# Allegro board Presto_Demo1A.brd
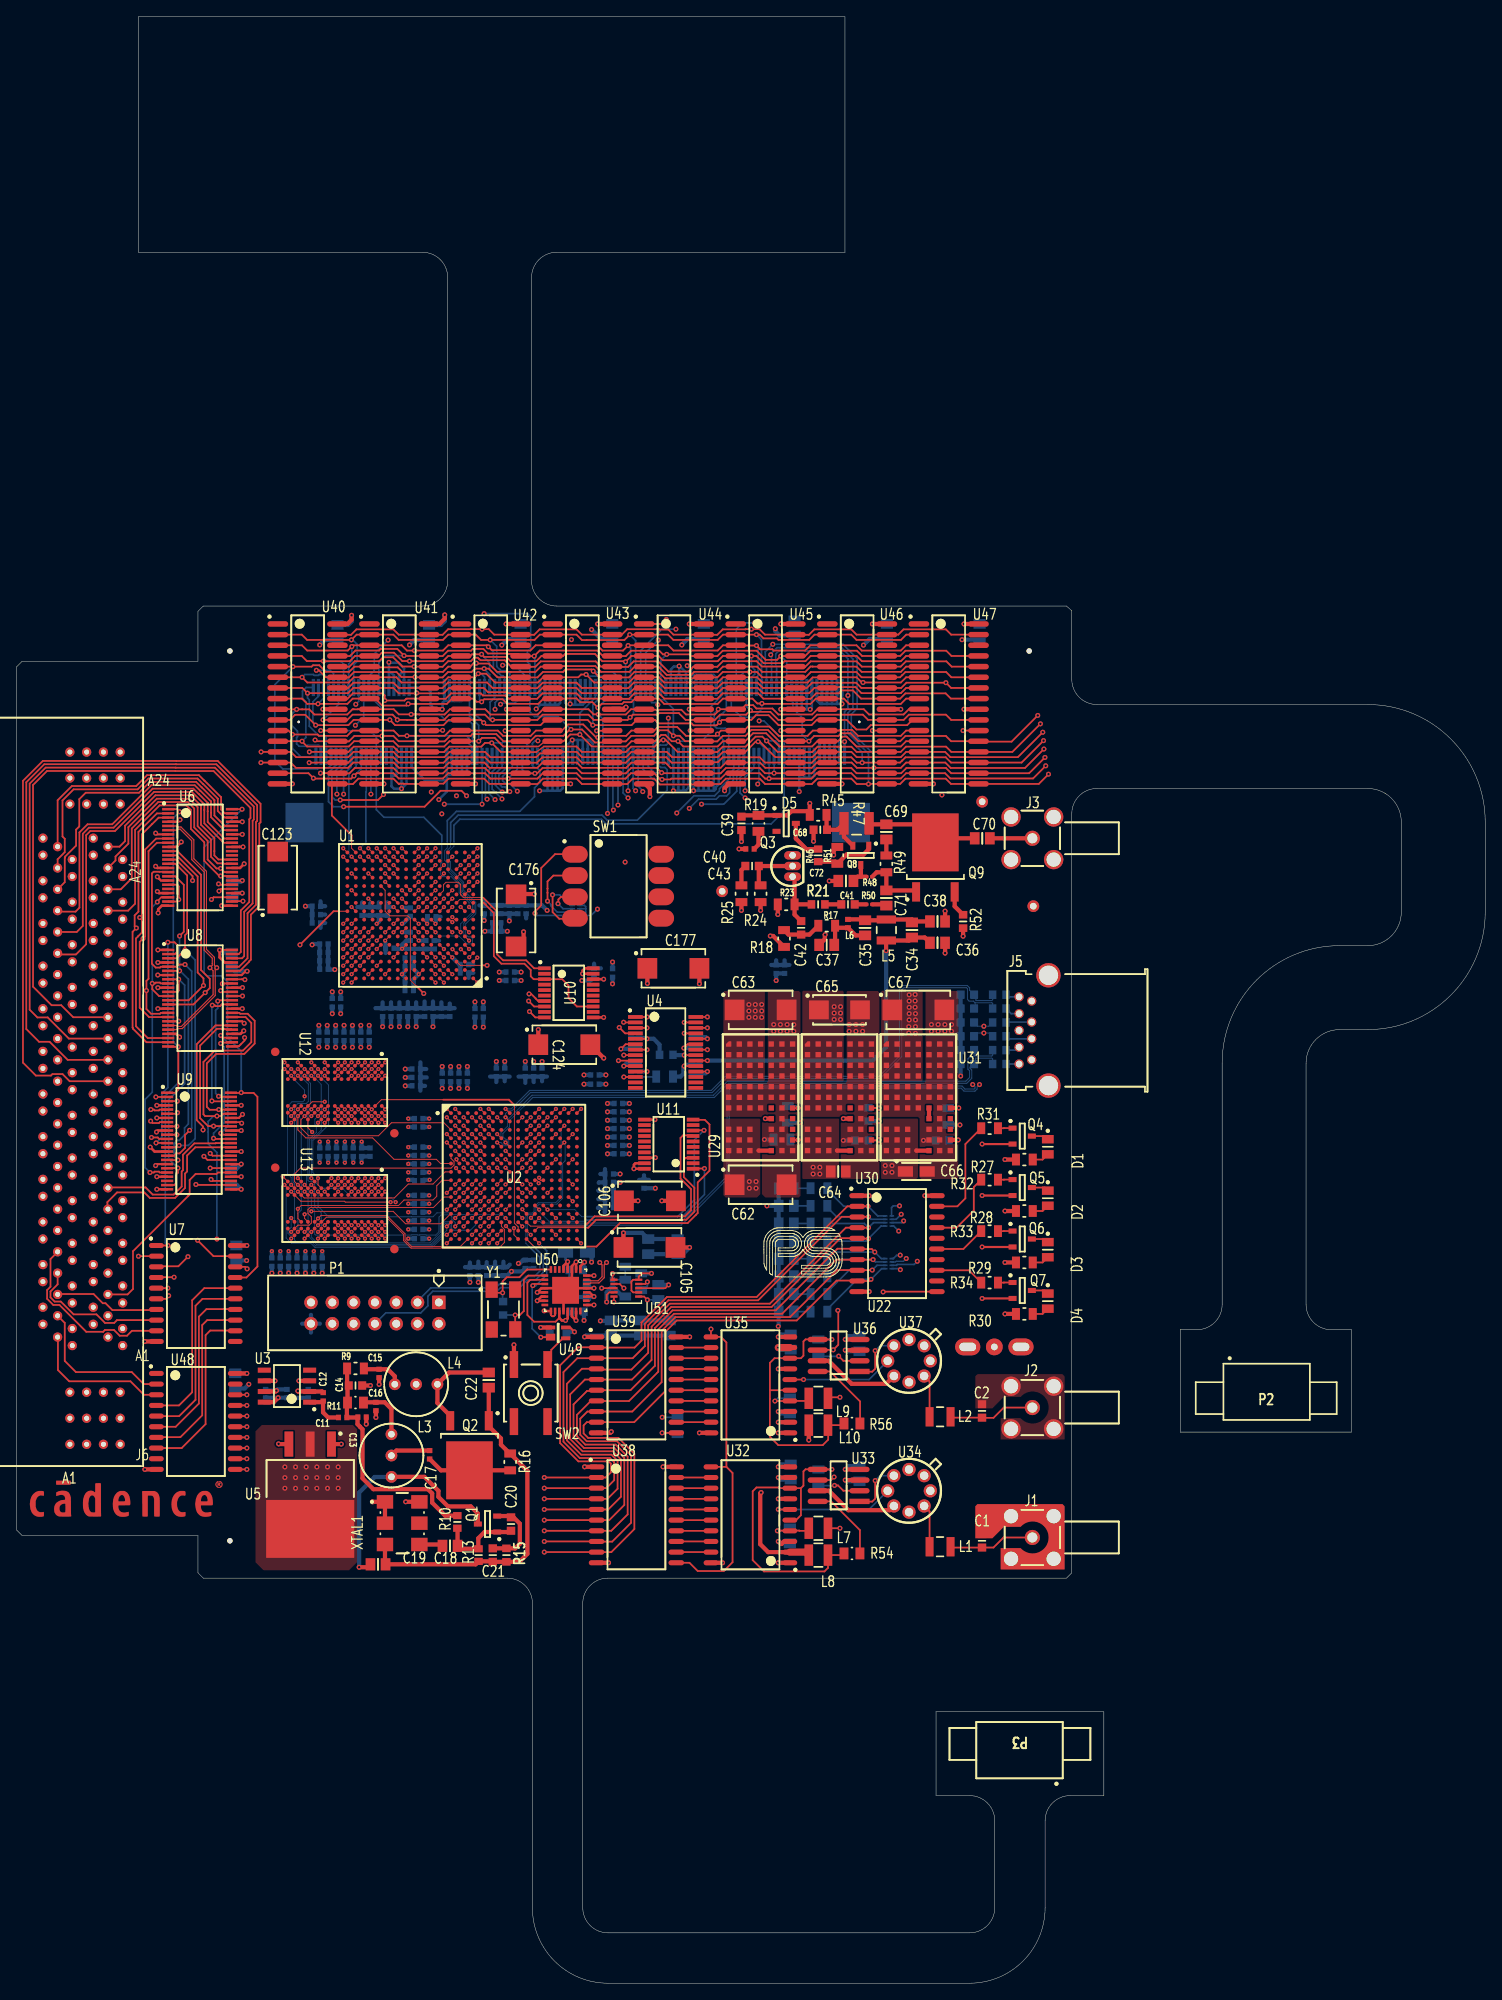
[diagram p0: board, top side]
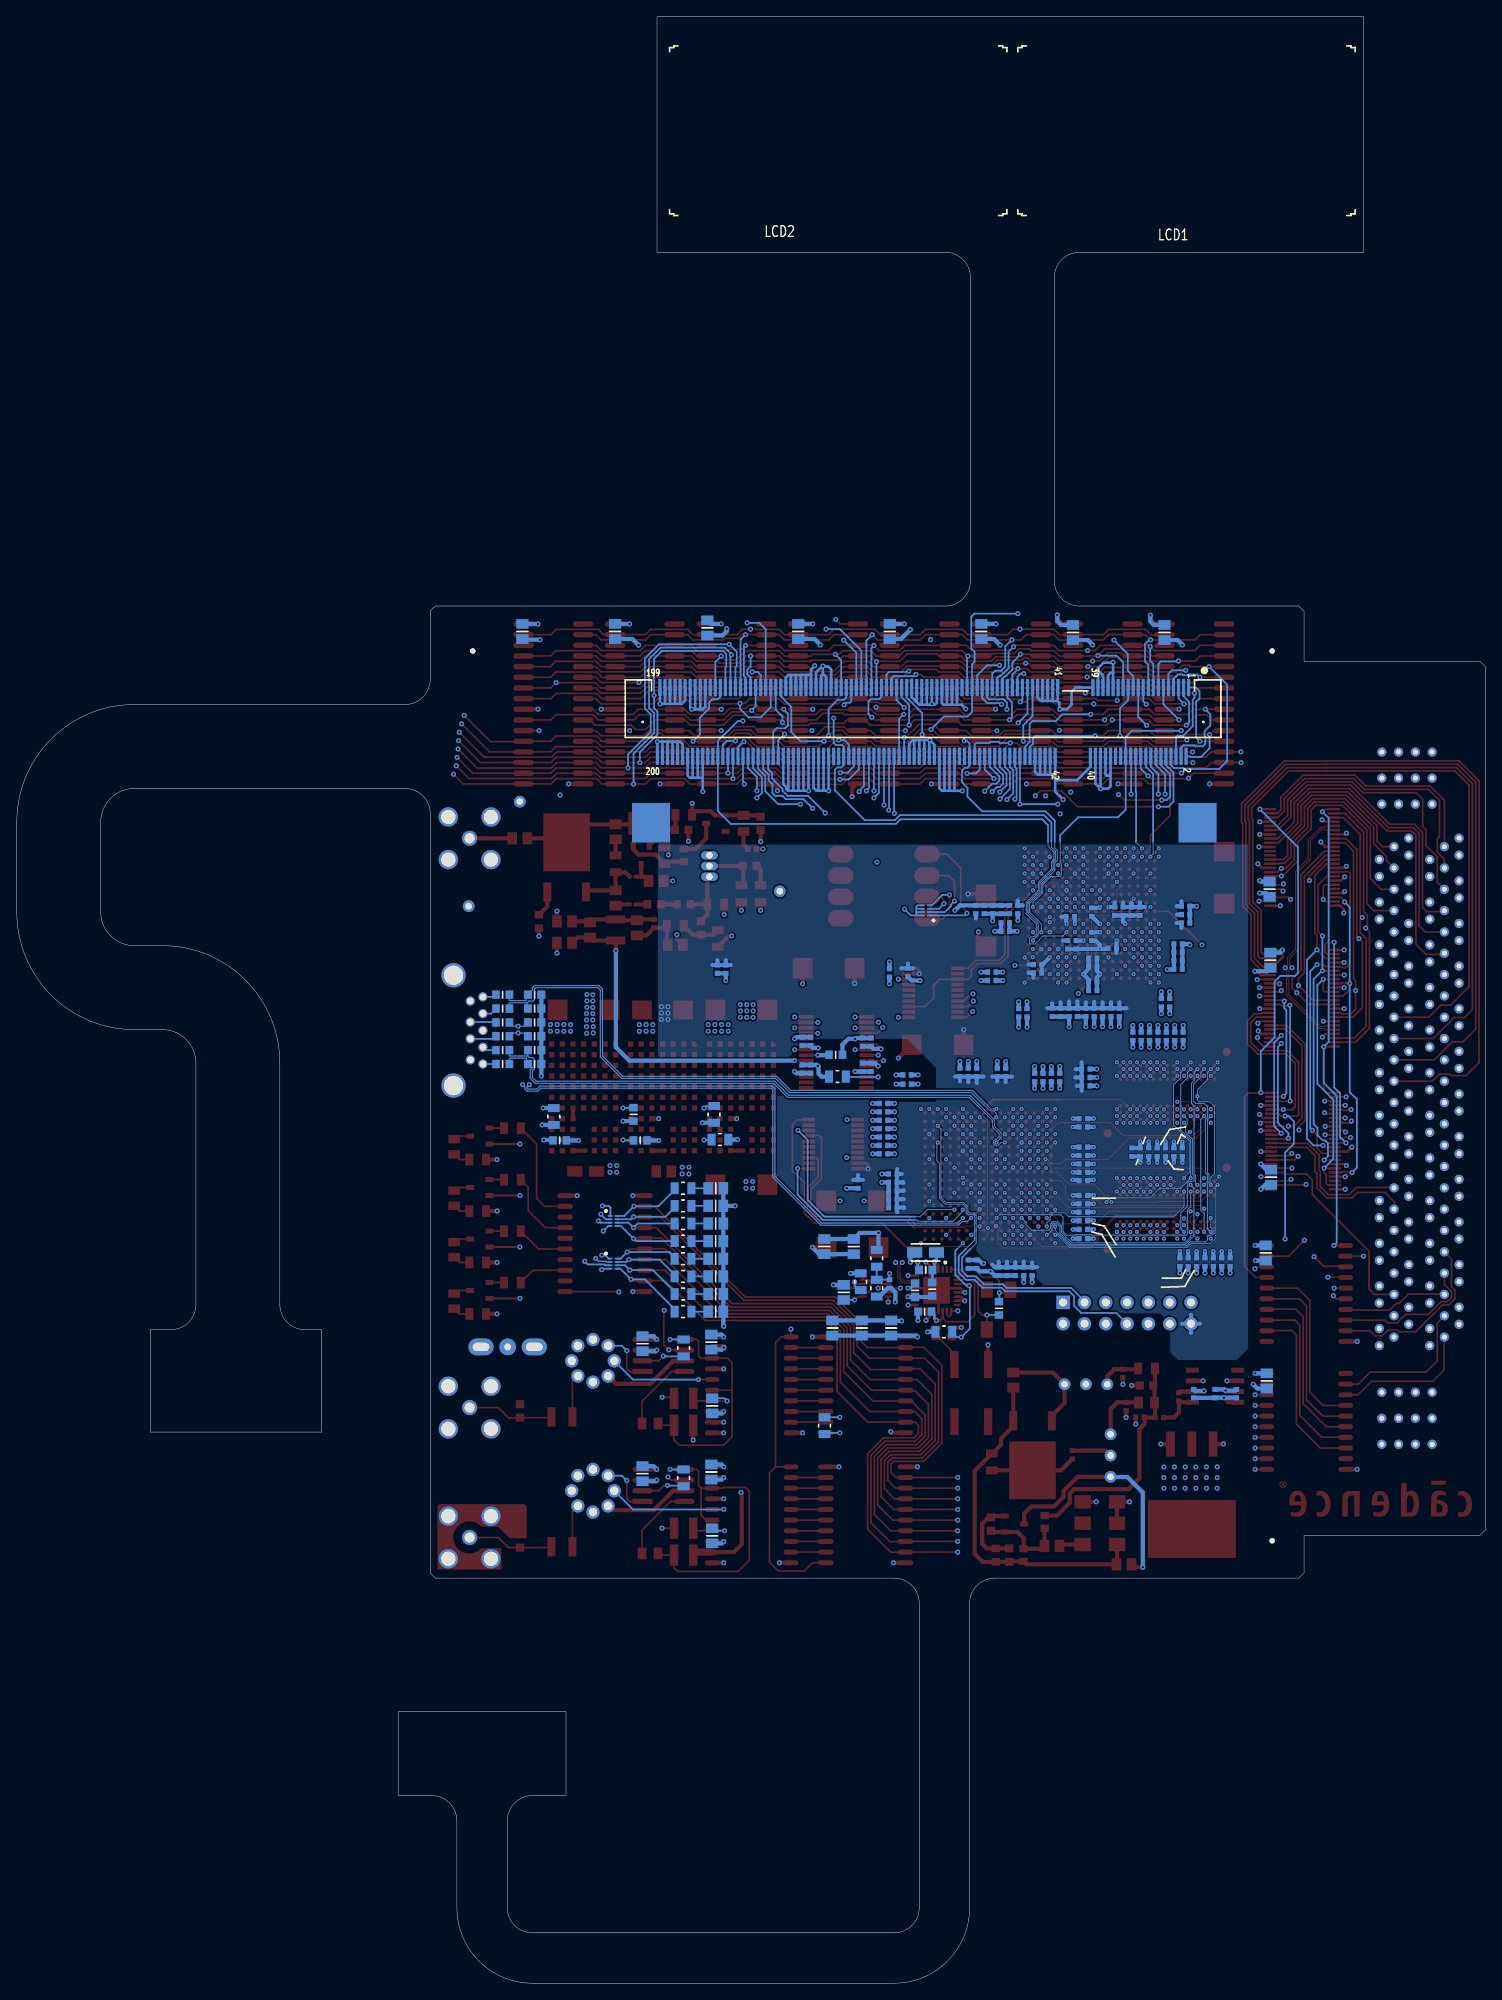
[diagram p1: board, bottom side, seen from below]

Outline 175 x 234.25 mm; copper layers: TOP, GND, INNER1, INNER2, POWER, BOTTOM. Coordinates in mm from the lower left corner of the outline.
Outline path: 0,156.84 0,53.97 0.63,53.34 21.59,53.34 21.59,48.89 22.22,48.26 58.45,48.26 arc(60.57,47.38) 61.45,45.26 61.45,9 arc(64.09,2.64) 70.45,0 113.55,0 arc(119.91,2.64) 122.55,9 122.55,19.35 arc(123.43,21.47) 125.55,22.35 129.55,22.35 129.55,32.35 109.55,32.35 109.55,22.35 113.55,22.35 arc(115.67,21.47) 116.55,19.35 116.55,9 arc(115.67,6.88) 113.55,6 70.45,6 arc(68.33,6.88) 67.45,9 67.45,45.26 arc(68.33,47.38) 70.45,48.26 125.09,48.26 125.73,48.89 125.73,139.32 arc(126.61,141.44) 128.73,142.32 161,142.32 arc(163.83,141.15) 165,138.32 165,127.6 arc(163.83,124.77) 161,123.6 157.65,123.6 arc(147.75,119.5) 143.65,109.6 143.65,80.85 arc(142.77,78.73) 140.65,77.85 138.65,77.85 138.65,65.65 159.05,65.65 159.05,77.85 156.65,77.85 arc(154.53,78.73) 153.65,80.85 153.65,109.6 arc(154.82,112.43) 157.65,113.6 161,113.6 arc(170.9,117.7) 175,127.6 175,138.32 arc(170.9,148.22) 161,152.32 128.73,152.32 arc(126.61,153.2) 125.73,155.32 125.73,163.49 125.09,164.06 64.35,164.06 arc(62.23,164.93) 61.35,167.06 61.35,203.2 arc(62.23,205.32) 64.35,206.2 98.7,206.2 98.7,234.25 14.5,234.25 14.5,206.2 48.35,206.2 arc(50.47,205.32) 51.35,203.2 51.35,167.06 arc(50.47,164.93) 48.35,164.06 22.22,164.06 21.59,163.42 21.59,157.48 0.63,157.48 0,156.84

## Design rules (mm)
constraint set DEFAULT: 
net group CLOCK: nets CLOCK+ CLOCK-
net group D: nets D+ D-
net group DATA1[0..9]: nets DATA1.CLKA DATA1.WSTAT_L
net group DP1: nets DIFF1+ DIFF1-
net group LED1: nets LED1 N828385
net group LED2: nets LED2 N852308
net group LED3: nets LED3 N852494
net group LED4: nets LED4 N852683
net group N62056: nets N62056 N62436
net group RF: nets DDS_OUT Q1E
net group STDA_SSRX: nets STDA_SSRX+ STDA_SSRX-
net group STDA_SSTX: nets STDA_SSTX+ STDA_SSTX-
net group VCLKC: nets CLKC VCLKC
net group ADDRESS: nets A0 A1 A2 A3 A4 A5 A6 A7 A8 A9 A10 A11 A12 A13 A14 A15 A16 A17 A18 A19 A20 A21 A22 A23
net group BUF_OUT: nets BUF_OUT N61996 N62230 N62316 N62564 N81780 N884986 Q2E
net group DATA: nets D0 D1 D2 D3 D4 D5 D6 D7 D9 D10 D11 D12 D13 D14 D15
net group DATA1.VD0: nets DATA1.VD0 N00671 VDX7
net group DATA1.VD1: nets DATA1.VD1 N00689 VDX6
net group DATA1.VD2: nets DATA1.VD2 N00703 VDX5
net group DATA1.VD3: nets DATA1.VD3 N00717 VDX4
net group DATA1.VD4: nets DATA1.VD4 N00827 VDX3
net group DATA1.VD5: nets DATA1.VD5 N00831 VDX2
net group DATA1.VD6: nets DATA1.VD6 N00835 VDX1
net group DATA1.VD7: nets DATA1.VD7 N00837 VDX0
net group DATA[0..20]: nets DATA.BA0 DATA.BA1 DATA.BA2 DATA.BA3 DATA.BD0 DATA.BD1 DATA.BD2 DATA.BD3 DATA.BD4 DATA.BD5 DATA.BD6 DATA.BD7 DATA.BD8 DATA.BD9 DATA.BD12 DATA.BD13 DATA.BD14 DATA.BD15 DATA.CLKB
net group DATA_DIFFS: nets DATA0+ DATA0- DATA1+ DATA1- DATA2+ DATA2- DATA3+ DATA3-
net group DDR_DQ: nets DDR_DQ0 DDR_DQ1 DDR_DQ2 DDR_DQ3 DDR_DQ4 DDR_DQ5 DDR_DQ6 DDR_DQ7 DDR_DQ8 DDR_DQ9 DDR_DQ10 DDR_DQ11 DDR_DQ12 DDR_DQ13 DDR_DQ14 DDR_DQ15 DDR_DQ16 DDR_DQ17 DDR_DQ18 DDR_DQ19 DDR_DQ20 DDR_DQ21 DDR_DQ22 DDR_DQ23 DDR_DQ24 DDR_DQ25 DDR_DQ26 DDR_DQ27 DDR_DQ28 DDR_DQ29 DDR_DQ30 DDR_DQ31
net group DDS[0..10]: nets DDS.DATA0 DDS.DATA1 DDS.DATA2 DDS.DATA3 DDS.DATA4 DDS.DATA5 DDS.DATA6 DDS.DATA7 DDS.FQUD DDS.RESET DDS.WCLK
net group MEMORY[0..29]: nets MEMORY.CTRL.RCS0 MEMORY.CTRL.RCS1 MEMORY.CTRL.RCS2 MEMORY.CTRL.RCS3 MEMORY.CTRL.RWE MEMORY.RA0 MEMORY.RA1 MEMORY.RA2 MEMORY.RA3 MEMORY.RA4 MEMORY.RA5 MEMORY.RA6 MEMORY.RA7 MEMORY.RA8 MEMORY.RA9 MEMORY.RA10 MEMORY.RA11 MEMORY.RA12 MEMORY.RA13 MEMORY.RA14 MEMORY.RA15 MEMORY.RA16 MEMORY.RD0 MEMORY.RD1 MEMORY.RD2 MEMORY.RD3 MEMORY.RD4 MEMORY.RD5 MEMORY.RD6 MEMORY.RD7
net group N00038_USER_DESIGN_OUTPUTS0_DAAMP0: nets N00038_USER_DESIGN_OUTPUTS0_DAAMP0 N00038_USER_DESIGN_OUTPUTS0_DAAMP1 N04966
net group N00046_USER_DESIGN_OUTPUTS0_DAAMP0: nets N00036_USER_DESIGN_OUTPUTS0_DAAMP0 N00046_USER_DESIGN_OUTPUTS0_DAAMP0 N00048_USER_DESIGN_OUTPUTS0_DAAMP0
net group N00046_USER_DESIGN_OUTPUTS0_DAAMP1: nets N00036_USER_DESIGN_OUTPUTS0_DAAMP1 N00046_USER_DESIGN_OUTPUTS0_DAAMP1 N00048_USER_DESIGN_OUTPUTS0_DAAMP1
net group N111881: nets N111502 N111881 N113142 N114006 N118214 N118917 N120412 N121910 N123723 N124926 N129422 N221560
net group POWER_GROUP: nets 5V
net group STEVE: nets N830942

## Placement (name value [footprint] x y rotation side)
C1  47 pF  [CAPC1608X86N]  115.03 52.7 90 top
C2  47 pF  [CAPC1608X86N]  115.03 68.17 90 top
C3  3300 pF  [CAPC2012X71N]  91.7 94.7 180 bottom
C4  3300 pF  [CAPC2012X71N]  91.7 86.3 180 bottom
C5  3300 pF  [CAPC2012X71N]  91.7 92.6 180 bottom
C6  3300 pF  [CAPC2012X71N]  91.7 84.2 180 bottom
C7  3300 pF  [CAPC2012X71N]  91.7 90.5 180 bottom
C8  3300 pF  [CAPC2012X71N]  91.7 82.1 180 bottom
C9  3300 pF  [CAPC2012X71N]  91.7 88.4 180 bottom
C10  3300 pF  [CAPC2012X71N]  91.7 80 180 bottom
C11  1000 pF  [CAPC1005X56N]  38.84 67.39 0 top
C12  1000 pF  [CAPC1005X56N]  36.52 69.85 270 top
C13  1000 pF  [CAPC1005X56N]  41.15 67.43 180 top
C14  0.01 uF  [CAPC1608X86N]  40.36 71.2 180 top
C15  1000 pF  [CAPC1005X56N]  43.18 72.64 90 top
C16  1000 pF  [CAPC1005X56N]  42.8 68.7 90 top
C17  1000 pF  [CAPC1005X56N]  49.2 62.95 270 top
C18  100 pF  [CAPC2012X70N]  51.63 52.1 180 top
C19  22 pF  [CAPC2012X71N]  43.05 49.9 0 top
C20  47 pF  [CAPC1608X86N]  58.9 54.7 90 top
C21  47 pF  [CAPC1608X86N]  56.73 51 90 top
C22  22 pF  [CAPC2012X71N]  56.25 71.85 270 top
C23  1000 pF  [CAPC1005X56N]  73.2 109.1 90 bottom
C24  1000 pF  [CAPC1005X56N]  81.4 108.9 90 bottom
C25  1000 pF  [CAPC1005X56N]  74.2 109.1 90 bottom
C26  1000 pF  [CAPC1005X56N]  80.4 108.9 90 bottom
C27  1000 pF  [CAPC1005X56N]  73.2 112.1 90 bottom
C28  1000 pF  [CAPC1005X56N]  80.4 112.2 90 bottom
C29  1000 pF  [CAPC1005X56N]  81.4 112.2 90 bottom
C30  1000 pF  [CAPC1005X56N]  74.2 112.1 90 bottom
C31  1000 pF  [CAPC1005X56N]  34.74 70.23 270 bottom
C32  1000 pF  [CAPC1005X56N]  32.2 70.23 270 bottom
C33  1000 pF  [CAPC1005X56N]  29.66 70.23 270 bottom
C34  3.3 pF  [CAPC2012X88N]  106.68 125.47 270 top
C35  8.2 pF  [CAPC2012X140N]  101.09 125.72 270 top
C36  22 pF  [CAPC2012X71N]  109.73 123.94 180 top
C37  22 pF  [CAPC2012X71N]  96.52 123.69 0 top
C38  33 pF  [CAPC2012X71N]  109.73 126.48 0 top
C39  0.01 uF  [CAPC1608X86N]  86.36 138.17 90 top
C40  1000 pF  [CAPC1005X56N]  87.38 135.12 0 top
C41  0.01 uF  [CAPC1608X86N]  99.06 128.51 0 top
C42  0.01 uF  [CAPC1608X86N]  93.47 125.72 90 top
C43  0.01 uF  [CAPC1608X86N]  87.63 133.09 0 top
C44  0.1 uF  [CAPC2012X100N]  25.53 96.01 270 bottom
C45  0.1 uF  [CAPC2012X100N]  26.16 86.99 270 bottom
C46  0.1 uF  [CAPC2012X100N]  25.6 121.86 90 bottom
C47  0.1 uF  [CAPC2012X100N]  25.7 130.33 270 bottom
C48  0.1 uF  [CAPC2012X100N]  92.7 161.45 270 bottom
C49  0.1 uF  [CAPC2012X100N]  49.13 160.9 270 bottom
C50  0.1 uF  [CAPC2012X100N]  103.7 161.03 270 bottom
C51  0.1 uF  [CAPC2012X100N]  60.05 161.03 270 bottom
C52  0.1 uF  [CAPC2012X100N]  81.88 161.03 270 bottom
C53  0.1 uF  [CAPC2012X100N]  38.22 160.9 270 bottom
C54  0.1 uF  [CAPC2012X100N]  70.96 161.03 270 bottom
C55  0.1 uF  [CAPC2012X100N]  114.74 161.03 270 bottom
C62  10 uF  [CAPMP7343X310N]  88.65 95.12 0 top
C63  100 uF  [CAPMP7343X310N]  88.65 115.95 0 top
C64  2.2 uF  [CAPC2012X71N]  97.9 96.7 0 top
C65  47 uF  [CAPMP6032X280N]  98.04 115.95 0 top
C66  4.7 uF  [CAPMP3216X180N]  107.2 96.7 0 top
C67  100 uF  [CAPMP7343X310N]  107.44 115.95 0 top
C68  0.01 uF  [CAPC1608X86N]  95.76 137.4 0 top
C69  0.47 uF  [CAPC2012X71N]  103.63 137.15 270 top
C70  0.47 uF  [CAPC2012X71N]  115.06 136.39 0 top
C71  0.47 uF  [CAPC2012X71N]  103.63 129.28 90 top
C72  0.01 uF  [CAPC2012X71N]  98.81 131.31 0 top
C73  22 pF  [CAPC1005X56N]  32.4 85.9 270 bottom
C74  22 pF  [CAPC1005X56N]  31.4 85.9 270 bottom
C75  22 pF  [CAPC1005X56N]  30.4 85.9 270 bottom
C76  22 pF  [CAPC1005X56N]  42.1 99 90 bottom
C77  22 pF  [CAPC1005X56N]  36.1 99 90 bottom
C78  22 pF  [CAPC1005X56N]  37.1 99 90 bottom
C79  22 pF  [CAPC1005X56N]  38.1 99 90 bottom
C80  22 pF  [CAPC1005X56N]  39.1 99 90 bottom
C81  220 pF  [CAPC1005X56N]  42 112.8 90 bottom
C82  220 pF  [CAPC1005X56N]  38 112.8 90 bottom
C83  220 pF  [CAPC1005X56N]  39 112.8 90 bottom
C84  220 pF  [CAPC1005X56N]  40 112.8 90 bottom
C85  2200 pF  [CAPC1005X56N]  47.9 95.6 180 bottom
C86  2200 pF  [CAPC1005X56N]  53.7 107.9 270 bottom
C87  2200 pF  [CAPC1005X56N]  51.7 107.9 270 bottom
C88  2200 pF  [CAPC1005X56N]  52.7 107.9 270 bottom
C89  22 pF  [CAPC1005X56N]  61.6 108.5 90 bottom
C90  22 pF  [CAPC1005X56N]  62.6 108.5 90 bottom
C91  22 pF  [CAPC1005X56N]  35.7 126.3 180 bottom
C92  22 pF  [CAPC1005X56N]  53.35 120.35 180 bottom
C93  22 pF  [CAPC1005X56N]  53.35 121.35 180 bottom
C94  22 pF  [CAPC1005X56N]  44.45 123.3 0 bottom
C95  22 pF  [CAPC1005X56N]  35.7 127.3 180 bottom
C96  22 pF  [CAPC1005X56N]  41.15 127.7 270 bottom
C97  22 pF  [CAPC1005X56N]  47.6 115.65 270 bottom
C98  22 pF  [CAPC1005X56N]  48.6 115.65 270 bottom
C99  220 pF  [CAPC1005X56N]  55 84.8 270 bottom
C100  220 pF  [CAPC1005X56N]  91.5 120.8 270 bottom
C101  220 pF  [CAPC1005X56N]  43.6 115.65 270 bottom
C102  220 pF  [CAPC1005X56N]  44.6 115.65 270 bottom
C103  220 pF  [CAPC1005X56N]  45.6 115.65 270 bottom
C104  220 pF  [CAPC1005X56N]  46.6 115.65 270 bottom
C105  470 uF  [CAPMP7343X430N]  75.4 87.65 0 top
C106  470 uF  [CAPMP7343X430N]  75.45 93.2 0 top
C107  22 pF  [CAPC1005X56N]  46.77 121.09 0 bottom
C108  22 pF  [CAPC1005X56N]  71 120.35 90 bottom
C109  22 pF  [CAPC1005X56N]  59.7 127.9 90 bottom
C110  22 pF  [CAPC1005X56N]  57.7 127.9 90 bottom
C111  22 pF  [CAPC1005X56N]  56.7 127.9 90 bottom
C112  220 pF  [CAPC1005X56N]  36.6 120.8 0 bottom
C113  220 pF  [CAPC1005X56N]  46.77 122.12 0 bottom
C114  220 pF  [CAPC1005X56N]  71.7 103.8 0 bottom
C115  2200 pF  [CAPC1005X56N]  71.7 101.8 0 bottom
C116  2200 pF  [CAPC1005X56N]  49.6 115.65 270 bottom
C117  220 pF  [CAPC1005X56N]  55.7 127.9 270 bottom
C118  220 pF  [CAPC1005X56N]  44.15 127.7 270 bottom
C119  220 pF  [CAPC1005X56N]  50.6 115.65 270 bottom
C120  2200 pF  [CAPC1005X56N]  42.15 127.7 270 bottom
C121  2200 pF  [CAPC1005X56N]  43.15 127.7 270 bottom
C122  2200 pF  [CAPC1005X56N]  49.75 123.7 270 bottom
C123  470 uF  [CAPMP7343X430N]  31.1 131.7 90 top
C124  470 uF  [CAPMP7343X430N]  65.25 111.8 0 top
C125  22 pF  [CAPC1005X56N]  47.9 103 180 bottom
C126  22 pF  [CAPC1005X56N]  47.9 102 180 bottom
C127  22 pF  [CAPC1005X56N]  46.9 124.7 270 bottom
C128  22 pF  [CAPC1005X56N]  46.9 127.6 270 bottom
C129  22 pF  [CAPC1005X56N]  57.2 126.31 0 bottom
C130  220 pF  [CAPC1005X56N]  55.6 115.6 270 bottom
C131  220 pF  [CAPC1005X56N]  54.6 115.6 270 bottom
C132  220 pF  [CAPC1005X56N]  37.6 116.8 270 bottom
C133  2200 pF  [CAPC1005X56N]  71.7 100.8 0 bottom
C134  22 pF  [CAPC1005X56N]  47.9 90.85 180 bottom
C135  22 pF  [CAPC1005X56N]  47.9 98.6 180 bottom
C136  22 pF  [CAPC1005X56N]  47.9 97.6 180 bottom
C137  22 pF  [CAPC1005X56N]  47.9 92.85 180 bottom
C138  22 pF  [CAPC1005X56N]  47.9 91.85 180 bottom
C139  22 pF  [CAPC1005X56N]  41 112.8 90 bottom
C140  220 pF  [CAPC1005X56N]  71.7 104.8 0 bottom
C141  220 pF  [CAPC1005X56N]  71.7 98.8 0 bottom
C142  2200 pF  [CAPC1005X56N]  47.9 99.6 180 bottom
C143  2200 pF  [CAPC1005X56N]  47.9 96.6 180 bottom
C144  22 pF  [CAPC1005X56N]  54 84.8 270 bottom
C145  22 pF  [CAPC1005X56N]  70.6 92.4 0 bottom
C146  22 pF  [CAPC1005X56N]  47.6 108.9 180 bottom
C147  22 pF  [CAPC1005X56N]  48.75 123.7 270 bottom
C148  22 pF  [CAPC1005X56N]  90.5 120.8 270 bottom
C149  22 pF  [CAPC1005X56N]  68.8 120.4 270 bottom
C150  22 pF  [CAPC1005X56N]  74.75 95.2 270 bottom
C151  22 pF  [CAPC1005X56N]  49.45 127.05 180 bottom
C152  22 pF  [CAPC1005X56N]  35.7 128.3 180 bottom
C153  22 pF  [CAPC1005X56N]  51.6 115.65 270 bottom
C154  220 pF  [CAPC1005X56N]  70.6 95.4 0 bottom
C155  220 pF  [CAPC1005X56N]  70.6 94.4 0 bottom
C156  220 pF  [CAPC1005X56N]  47.6 106.9 180 bottom
C157  220 pF  [CAPC1005X56N]  70.6 93.4 0 bottom
C158  220 pF  [CAPC1005X56N]  58.15 108.5 90 bottom
C159  220 pF  [CAPC1005X56N]  60.6 108.5 90 bottom
C160  22 pF  [CAPC1005X56N]  36.6 122.8 0 bottom
C161  22 pF  [CAPC1005X56N]  46.77 119.29 0 bottom
C162  22 pF  [CAPC1005X56N]  58.7 127.9 90 bottom
C163  22 pF  [CAPC1005X56N]  36.6 123.8 0 bottom
C164  22 pF  [CAPC1005X56N]  46.77 118.26 0 bottom
C165  220 pF  [CAPC1005X56N]  58.8 120.45 0 bottom
C166  220 pF  [CAPC1005X56N]  58.8 119.45 0 bottom
C167  220 pF  [CAPC1005X56N]  36.6 121.8 0 bottom
C168  2200 pF  [CAPC1005X56N]  71.7 102.8 0 bottom
C169  2200 pF  [CAPC1005X56N]  60.7 127.9 90 bottom
C170  220 pF  [CAPC1005X56N]  56 84.8 270 bottom
C171  220 pF  [CAPC1005X56N]  47.6 107.9 180 bottom
C172  220 pF  [CAPC1005X56N]  57.15 108.5 90 bottom
C173  2200 pF  [CAPC1005X56N]  70.6 96.4 0 bottom
C174  2200 pF  [CAPC1005X56N]  58 84.8 270 bottom
C175  2200 pF  [CAPC1005X56N]  57 84.8 270 bottom
C176  470 uF  [CAPMP7343X430N]  59.5 126.6 270 top
C177  470 uF  [CAPMP7343X430N]  78.25 120.9 0 top
C178  22 pF  [CAPC1005X56N]  60.6 85.65 270 bottom
C179  22 pF  [CAPC1005X56N]  47.9 89.8 180 bottom
C180  22 pF  [CAPC1005X56N]  47.9 88.7 180 bottom
C181  22 pF  [CAPC1005X56N]  68.9 107.1 180 bottom
C182  22 pF  [CAPC1005X56N]  68.9 108.2 180 bottom
C183  220 pF  [CAPC1005X56N]  57.2 125.31 0 bottom
C184  220 pF  [CAPC1005X56N]  38.6 116.8 270 bottom
C185  220 pF  [CAPC1005X56N]  61.6 85.65 270 bottom
C186  2200 pF  [CAPC1005X56N]  71.7 99.8 0 bottom
C187  22 pF  [CAPC1005X56N]  36.4 85.9 270 bottom
C188  22 pF  [CAPC1005X56N]  40.1 99 90 bottom
C189  22 pF  [CAPC1005X56N]  34.4 85.9 270 bottom
C190  22 pF  [CAPC1005X56N]  33.4 85.9 270 bottom
C191  22 pF  [CAPC1005X56N]  41.1 99 90 bottom
C192  22 pF  [CAPC1005X56N]  35.4 85.9 270 bottom
C193  220 pF  [CAPC1005X56N]  36 112.8 90 bottom
C194  220 pF  [CAPC1005X56N]  37 112.8 90 bottom
C195  2200 pF  [CAPC1005X56N]  50.7 107.9 270 bottom
C196  2200 pF  [CAPC1005X56N]  47.9 93.85 180 bottom
C197  0.1 uF  [CAPC2012X100N]  92.23 60.9 90 bottom
C198  0.1 uF  [CAPC2012X100N]  92.13 53.3 270 bottom
C199  0.1 uF  [CAPC2012X100N]  100.43 60.7 270 bottom
C200  0.1 uF  [CAPC2012X100N]  92.23 76.38 90 bottom
C201  0.1 uF  [CAPC2012X100N]  92.13 68.78 270 bottom
C202  0.1 uF  [CAPC2012X100N]  100.43 76.18 270 bottom
C2000  33 pF  [CAPC1608X86N]  113.28 114.45 180 bottom
C2001  33 pF  [CAPC1608X86N]  113.28 112.8 180 bottom
C2002  33 pF  [CAPC1608X86N]  113.28 116.11 180 bottom
C2003  33 pF  [CAPC1608X86N]  113.28 117.76 180 bottom
C2004  33 pF  [CAPC1608X86N]  113.28 109.5 180 bottom
C2005  33 pF  [CAPC1608X86N]  113.28 111.15 180 bottom
C2006  0.1 uF  [CAPC2012X100N]  26.04 71.75 270 bottom
C2007  0.01 uF  [CAPC1608X86N]  67.94 82.55 270 bottom
C2008  22 uF  [CAPMP3216X120N]  66.7 87.05 0 bottom
C2009  0.01 uF  [CAPC1608X86N]  66.67 84.96 0 bottom
C2010  1000 pF  [CAPC1005X56N]  70.99 83.31 270 bottom
C2011  0.1 uF  [CAPC2012X100N]  77.8 78.05 270 bottom
C2012  0.1 uF  [CAPC2012X100N]  74.3 78.05 270 bottom
C2013  0.1 uF  [CAPC2012X100N]  70.8 78.05 270 bottom
C2014  0.1 uF  [CAPC2012X100N]  78.75 87.75 270 bottom
C2015  0.1 uF  [CAPC2012X100N]  75.25 87.75 270 bottom
C2016  0.1 uF  [CAPC2012X100N]  76.45 82.29 90 bottom
D1  GREEN  [LEDC2012X120N]  122.87 99.64 270 top
D2  GREEN  [LEDC2012X120N]  122.87 93.51 270 top
D3  GREEN  [LEDC2012X120N]  122.87 87.38 270 top
D4  GREEN  [LEDC2012X120N]  122.87 81.25 270 top
D5  MMBD4148  [SOT95P230X109-3N]  91.69 138.17 0 top
J1  901-9894-RFX  [SMB_90]  121.03 53.1 270 top
J2  901-9894-RFX  [SMB_90]  121.03 68.58 270 top
J3  901-9894-RFX  [SMB_90]  121.03 136.39 270 top
J5  AU-Y1005-3-R  [USB3A_FEMALE]  119.45 113.5 90 top
J6  6367550-6  [C-1367550-6]  6.33 64.2 90 top
J7  1473005-1  [C_1_1473005_1_J1]  66.85 150.25 270 bottom
L1  47 nH  [INDC2520X220N]  110.03 52 0 top
L2  47 nH  [INDC2520X220N]  110.03 67.48 0 top
L3  INDUCTOR3  [TOROID01_3]  44.65 65.4 270 top
L4  INDUCTOR3  [TOROID01_3]  45.05 71.35 0 top
L5  1.0 uH  [INDC2520X220N]  103.63 125.47 90 top
L6  6.8 nH  [INDC1005X60N]  99.06 126.23 270 top
L7  56 nH  [IND_CENTRAL_1008]  95.53 54.2 180 top
L8  56 nH  [IND_CENTRAL_1008]  95.53 51 0 top
L9  56 nH  [IND_CENTRAL_1008]  95.53 69.68 180 top
L10  56 nH  [IND_CENTRAL_1008]  95.53 66.48 0 top
LCD1  S1D13742F01A200  [LCD_EA_8081-A3N-B]  35.6 220.68 180 bottom
LCD2  S1D13742F01A200  [LCD_EA_8081-A3N-B]  77.1 220.68 180 bottom
NOREF  -  []  25.4 52.7 0 top
NOREF#2  -  [unnamed#2]  116.5 75.8 0 top
NOREF#3  -  [unnamed#3]  120.65 158.7 0 top
NOREF#4  -  [unnamed#3]  25.4 158.7 0 top
NOREF#5  -  [unnamed#4]  70.6 121.7 0 top
NOREF#6  -  []  25.4 52.7 0 top
NOREF#7  -  [unnamed#3]  25.4 52.7 0 top
NOREF#8  -  []  -0.13 150.49 0 top
P1  TST-107-01-G-D  [SAMTEC_TST-107-XX-X-D]  50.3 81.1 180 top
P2  53261-0819  [MOLEX_53261-8_FITNAIL]  148.9 69.7 0 top
P3  53261-0819  [MOLEX_53261-8_FITNAIL]  119.55 28.51 180 top
Q1  2N2222AUB  [SOT95P230X109-3N]  56.1 54.7 180 top
Q2  MMBFJ310LT1G  [TO230P950X240-3N]  53.95 62.9 270 top
Q3  2N3866  [TO92]  92.46 131.82 180 top
Q4  KST3904  [SOT95P240X114-3N]  119.82 100.91 0 top
Q5  KST3904  [SOT95P240X114-3N]  119.82 94.78 0 top
Q6  KST3904  [SOT95P240X114-3N]  119.82 88.65 0 top
Q7  KST3904  [SOT95P240X114-3N]  119.82 82.52 0 top
Q8  2N3905  [SOT95P230X109-3N]  100.58 134.36 270 top
Q9  2N5179-NRC  [TO230P950X240-3N]  109.47 134.1 90 top
R1  243 Ohm  [RESC2012X60N]  95.6 94.7 0 bottom
R2  243 Ohm  [RESC2012X60N]  95.6 86.3 0 bottom
R3  243 Ohm  [RESC2012X60N]  95.6 92.6 0 bottom
R4  243 Ohm  [RESC2012X60N]  95.6 84.2 0 bottom
R5  243 Ohm  [RESC2012X60N]  95.6 90.5 0 bottom
R6  243 Ohm  [RESC2012X60N]  95.6 82.1 0 bottom
R7  243 Ohm  [RESC2012X60N]  95.6 88.4 0 bottom
R8  243 Ohm  [RESC2012X60N]  95.6 80 0 bottom
R9  330 Ohm  [RESC2012X60N]  40.36 73.23 180 top
R10  10 kOhm  [RESC1608X50N]  52.5 54.95 90 top
R11  97.6 Ohm  [RESC2012X70N]  40.36 69.17 0 top
R12  2.0 kOhm  [RESC1608X55N]  77.4 110.6 0 bottom
R13  10 kOhm  [RESC1608X50N]  55.03 51 90 top
R14  3.9 kOhm  [RESC2012X50N]  77.2 108 180 bottom
R15  2.0 kOhm  [RESC1608X55N]  58.35 51 90 top
R16  220 Ohm  [RESC2012X60N]  58.8 62.1 270 top
R17  180 Ohm  [RESC2012X60N]  96.52 125.97 180 top
R18  56 Ohm  [RESC2012X60N]  91.44 124.45 90 top
R19  97.6 Ohm  [RESC2012X70N]  88.39 138.17 90 top
R21  2.0 kOhm  [RESC1608X55N]  95.5 128.51 0 top
R23  470 Ohm  [RESC2012X60N]  91.69 128.51 0 top
R24  56 Ohm  [RESC2012X60N]  88.65 129.78 90 top
R25  56 Ohm  [RESC2012X60N]  86.36 129.78 90 top
R26  49.9 Ohm  [RESC2012X60N]  78.74 66.42 270 bottom
R27  470 Ohm  [RESC2012X60N]  120.08 98.12 0 top
R28  470 Ohm  [RESC2012X60N]  120.08 91.99 0 top
R29  470 Ohm  [RESC2012X60N]  120.08 85.86 0 top
R30  470 Ohm  [RESC2012X60N]  120.08 79.73 0 top
R31  150 Ohm  [RESC2012X60N]  115.94 101.85 0 top
R32  150 Ohm  [RESC2012X60N]  115.94 95.72 0 top
R33  150 Ohm  [RESC2012X60N]  115.94 89.59 0 top
R34  150 Ohm  [RESC2012X60N]  115.94 83.46 0 top
R39  105 kOhm  [RESC2012X60N]  91.9 103.5 270 bottom
R40  953 kOhm  [RESC2012X60N]  91.2 100.5 180 bottom
R41  61.9 kOhm  [RESC1608X55N]  101.5 103.5 270 bottom
R42  226 kOhm  [RESC1608X55N]  100.7 100.4 180 bottom
R43  118 kOhm  [RESC2012X60N]  111 103.25 270 bottom
R44  154 kOhm  [RESC1608X55N]  110.3 100.4 180 bottom
R45  470 Ohm  [RESC2012X60N]  95.5 139.18 180 top
R46  3.0 kOhm  [RESC1608X50N]  95.5 134.36 90 top
R47  270 Ohm  [RESC3225X70N]  100.08 138.17 180 top
R48  24 kOhm  [RESC0603X26N]  101.6 131.82 180 top
R49  470 Ohm  [RESC2012X60N]  103.63 133.34 90 top
R50  49.9 Ohm  [RESC0603X30N]  101.6 128.51 0 top
R51  6.8 kOhm  [RESC2012X60N]  97.79 134.36 90 top
R52  3.3 Ohm  [RESC1608X55N]  112.78 126.48 90 top
R53  97.6 Ohm  [RESC2012X50N]  95.53 60.2 270 bottom
R54  97.6 Ohm  [RESC2012X70N]  99.53 51.2 0 top
R55  97.6 Ohm  [RESC2012X50N]  95.53 75.68 270 bottom
R56  97.6 Ohm  [RESC2012X70N]  99.53 66.67 0 top
R2000  27.4 Ohm  [RESC1608X55N]  117.09 112.8 180 bottom
R2001  27.4 Ohm  [RESC1608X55N]  117.09 114.45 180 bottom
R2002  27.4 Ohm  [RESC1608X55N]  117.09 117.76 180 bottom
R2003  27.4 Ohm  [RESC1608X55N]  117.09 116.11 180 bottom
R2004  27.4 Ohm  [RESC1608X55N]  117.09 111.15 180 bottom
R2005  27.4 Ohm  [RESC1608X55N]  117.09 109.5 180 bottom
R2006  10  [RESC1608X55N]  65.91 82.67 90 bottom
R2007  2.0 kOhm  [RESC1608X55N]  66.8 80 0 bottom
R2008  100 kOhm  [RESC2012X60N]  64.52 77.59 180 bottom
R2009  2.0 kOhm  [RESC1608X55N]  57.95 80.4 90 bottom
R2010  10 kOhm  [RESC2012X60N]  72.52 86.36 270 bottom
R2011  10 kOhm  [RESC2012X60N]  72.52 82.8 270 bottom
R2012  100 kOhm  [RESC2012X60N]  74.42 83.56 270 bottom
RN1  47 Ohms  [RESNET_8]  66.65 127.8 0 bottom
RN2  100 Ohm  [RESNET_8]  103.89 85.72 180 bottom
RN3  100 Ohm  [RESNET_8]  103.89 90.8 180 bottom
SW1  76HPSB04GWRT  [SOIC254P1077X800-8M]  71.12 130.68 0 top
SW2  EVQPH  [SW_EVQ-PH_NO_GND]  61.25 70.3 0 top
U1  XC6SLX25-3FTG256  [FT256]  46.9 127.2 180 top
U2  XC6SLX25-3FTG256  [FT256]  59.25 96.15 0 top
U3  L78L08ACD13TR  [SOIC127P600X175-8N]  32.2 71.12 180 top
U4  AD9850BRSZ  [SOP65P780X200-28N]  77.32 110.88 0 top
U5  LM340  [TO254P1410X464-4N]  34.97 58.22 270 top
U6  74ALVT16245DGG,118  [SOP50P810X110-48N]  21.84 134.11 0 top
U7  74ACT245  [SOIC127P1028X265-20N]  21.34 82.16 0 top
U8  74ALVT16245DGG,118  [SOP50P810X110-48N]  21.84 117.34 0 top
U9  74ALVT16245DGG,118  [SOP50P810X110-48N]  21.72 100.33 0 top
U10  XCF01SVOG20C  [XCF01SVOG20]  65.79 117.98 0 top
U11  XCF01SVOG20C  [XCF01SVOG20]  77.7 99.95 180 top
U12  MT47H64M16HR-3:G TR  [MT47H128M]  37.9 106.1 270 top
U13  MT47H64M16HR-3:G TR  [MT47H128M]  37.9 92.3 270 top
U22  74HCT574  [SOIC127P1032X265-20AN]  104.9 88.1 0 top
U29  LTM8025EV#PBF  [LTUMODULE7X11]  88.65 105.53 0 top
U30  LTM8025EV#PBF  [LTUMODULE7X11]  98.04 105.53 0 top
U31  LTM8025EV#PBF  [LTUMODULE7X11]  107.44 105.53 0 top
U32  TLC5602CDWR  [SOIC127P1028X265-20N]  87.43 55.8 180 top
U33  DG419CY+  [SOG0508WG244L225]  100.43 57.4 90 top
U34  TLE2037AQDRG4Q1  [TO99]  106.33 61.2 180 top
U35  TLC5602CDWR  [SOIC127P1028X265-20N]  87.43 71.28 180 top
U36  DG419CY+  [SOG0508WG244L225]  100.43 72.88 90 top
U37  TLE2037AQDRG4Q1  [TO99]  106.33 76.68 180 top
U38  74HCT574  [SOIC127P1032X265-20AN]  73.84 55.8 0 top
U39  74HCT574  [SOIC127P1032X265-20AN]  73.84 71.28 0 top
U40  UPD431000AGW-B15  [SOJ127P866X375-32N]  34.66 152.39 0 top
U41  UPD431000AGW-B15  [SOJ127P866X375-32N]  45.58 152.39 0 top
U42  UPD431000AGW-B15  [SOJ127P866X375-32N]  56.49 152.39 0 top
U43  UPD431000AGW-B15  [SOJ127P866X375-32N]  67.41 152.39 0 top
U44  UPD431000AGW-B15  [SOJ127P866X375-32N]  78.32 152.39 0 top
U45  UPD431000AGW-B15  [SOJ127P866X375-32N]  89.23 152.39 0 top
U46  UPD431000AGW-B15  [SOJ127P866X375-32N]  100.15 152.39 0 top
U47  UPD431000AGW-B15  [SOJ127P866X375-32N]  111.06 152.39 0 top
U48  74ACT245  [SOIC127P1028X265-20N]  21.34 66.92 0 top
U49  MAX6711S  [SOT343N]  64.52 77.47 0 top
U50  NBC12429AMNR4G  [QFN50P500X500X100-33N]  65.41 82.55 270 top
U51  TPS51200DRCR  [DRC10_2P4X1P65]  72.64 82.8 0 top
XTAL1  100 MHz  [OSCSC254P500X700X200-6N]  45.93 54.8 0 top
Y1  20 MHz  [OSCCC350X600X120N]  58 80.25 0.2 top

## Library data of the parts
C1 = CAP: room: CHAN1
C2 = CAP: room: CHAN2
C3-C10 = CAP: signal model: DEFAULT_CAPACITOR_3300pF_1_2
C11-C13 C15-C17 C31-C33 = CAP: signal model: DEFAULT_CAPACITOR_1000pF_1_2
C14 = CAP: signal model: DEFAULT_CAPACITOR_10000pF_1_2
C18 = CAP: signal model: DEFAULT_CAPACITOR_100.000000pF_1_2
C19 C22 C73-C80 C89-C98 C125-C129 C134-C139 C144-C153 C178-C182 C187-C192 = CAP: signal model: DEFAULT_CAPACITOR_22.000000pF_1_2
C20 C21 = CAP: signal model: DEFAULT_CAPACITOR_47.000000pF_1_2
C23-C30 C107-C115 C160-C168 C2000-C2005 C2007 C2009-C2016 = CAP
C34-C43 = CAP: room: RF-AMP
C44-C47 C2006 = CAP: signal model: DEFAULT_CAPACITOR_100000pF_1_2
C48-C55 = CAP: signal model: DEFAULT_CAPACITOR_100000pF_1_2; room: BOTTOM_MEM
C62 = CAP_P: signal model: DEFAULT_CAPACITOR_1e+07pF_1_2
C63 = CAP_P: signal model: DEFAULT_CAPACITOR_1e+08pF_1_2
C64 = CAP: signal model: DEFAULT_CAPACITOR_2.2e+06pF_1_2
C65 = CAP_P: signal model: DEFAULT_CAPACITOR_4.7e+07pF_1_2
C66 = CAP_P: signal model: DEFAULT_CAPACITOR_4.7e+06pF_1_2
C67 C2008 = CAP_P
C68 C72 = CAP: signal model: DEFAULT_CAPACITOR_10000pF_1_2; room: RF-AMP
C69-C71 = CAP: signal model: DEFAULT_CAPACITOR_470000pF_1_2; room: RF-AMP
C81-C84 C99-C104 C117-C119 C130-C132 C140 C141 C154-C159 C170-C172 C183-C185 C193 C194 = CAP: signal model: DEFAULT_CAPACITOR_220.000000pF_1_2
C85-C88 C116 C120-C122 C133 C142 C143 C169 C173-C175 C186 C195 C196 = CAP: signal model: DEFAULT_CAPACITOR_2200pF_1_2
C105 C106 C123 C124 C176 C177 = CAP_P: signal model: DEFAULT_CAPACITOR_4.7e+08pF_1_2
C197-C199 = CAP: signal model: DEFAULT_CAPACITOR_100000pF_1_2; room: CHAN1
C200-C202 = CAP: signal model: DEFAULT_CAPACITOR_100000pF_1_2; room: CHAN2
D1-D4 = LED
D5 = DIODE_A_NC_C: room: RF-AMP
J1 = BNC-4: User Part Number: PSL-00000003; room: CHAN1
J2 = BNC-4: User Part Number: PSL-00000003; room: CHAN2
J3 = BNC-4: User Part Number: PSL-00000003
J5 = usb3a_female: User Part Number: PSL-00000013
J6 = CONN_C1367550_6
J7 = conn_dimm_200: room: BOTTOM_MEM
L1 = IND: room: CHAN1
L2 = IND: room: CHAN2
L3 L4 = INDUCTOR3
L5 L6 = IND: room: RF-AMP
L7 L8 = IND: signal model: DEFAULT_INDUCTOR_56.000000nH_1_2; room: CHAN1
L9 L10 = IND: signal model: DEFAULT_INDUCTOR_56.000000nH_1_2; room: CHAN2
LCD1 LCD2 = LCD-EA-8081-A3N
P1 = HDR_2X7_M
P2 P3 = HDR_1X8_M
Q1 Q4-Q7 = BJT_NPN_BEC
Q2 = MOSFET_I_EN_GSD
Q3 Q9 = BJT_NPN_BEC: room: RF-AMP
Q8 = BJT_PNP_BCE: room: RF-AMP
R1-R8 = RES: signal model: DEFAULT_RESISTOR_243.000000OHM_1_2
R9 = RES: signal model: DEFAULT_RESISTOR_330.000000OHM_1_2
R10 R13 = RES: signal model: DEFAULT_RESISTOR_10000OHM_1_2
R11 = RES: signal model: DEFAULT_RESISTOR_97.600000OHM_1_2
R12 R15 = RES: signal model: DEFAULT_RESISTOR_2000OHM_1_2
R14 = RES: signal model: DEFAULT_RESISTOR_3900OHM_1_2
R16 = RES: signal model: DEFAULT_RESISTOR_220.000000OHM_1_2
R17-R19 R21 R23-R25 = RES: room: RF-AMP
R26 = RES: signal model: DEFAULT_RESISTOR_49.900000OHM_1_2
R27-R30 = RES: signal model: DEFAULT_RESISTOR_470.000000OHM_1_2
R31-R34 = RES: signal model: DEFAULT_RESISTOR_150.000000OHM_1_2
R39 = RES: signal model: DEFAULT_RESISTOR_105000OHM_1_2
R40 = RES: signal model: DEFAULT_RESISTOR_953000OHM_1_2
R41 = RES: signal model: DEFAULT_RESISTOR_61900OHM_1_2
R42 = RES: signal model: DEFAULT_RESISTOR_226000OHM_1_2
R43 = RES: signal model: DEFAULT_RESISTOR_118000OHM_1_2
R44 = RES: signal model: DEFAULT_RESISTOR_154000OHM_1_2
R45 R49 = RES: signal model: DEFAULT_RESISTOR_470.000000OHM_1_2; room: RF-AMP
R46 = RES: signal model: DEFAULT_RESISTOR_3000OHM_1_2; room: RF-AMP
R47 = RES: signal model: DEFAULT_RESISTOR_270.000000OHM_1_2; room: RF-AMP
R48 = RES: signal model: DEFAULT_RESISTOR_24000OHM_1_2; room: RF-AMP
R50 = RES: signal model: DEFAULT_RESISTOR_49.900000OHM_1_2; room: RF-AMP
R51 = RES: signal model: DEFAULT_RESISTOR_6800OHM_1_2; room: RF-AMP
R52 = RES: signal model: DEFAULT_RESISTOR_3.300000OHM_1_2; room: RF-AMP
R53 R54 = RES: signal model: DEFAULT_RESISTOR_97.600000OHM_1_2; room: CHAN1
R55 R56 = RES: signal model: DEFAULT_RESISTOR_97.600000OHM_1_2; room: CHAN2
R2000-R2012 = RES
RN1 = RES_net_8
RN2 RN3 = RES_net_8: signal model: DEFAULT_RESISTOR_PACK_4_100.000000OHM
SW1 = SW DIP-4/SM
SW2 = SW_SPST_13_24
U1 = DemoG_Interface
U2 = DemoG_CoProc
U3 = LM78L05_SO8
U4 = AD9850
U5 = VREG_TGND
U6 U8 U9 = FCT16245
U7 U48 = 74-245_20P
U10 U11 = xcf01svog20
U12 U13 = MT47H64M16
U22 U38 U39 = FF_D_8X_OE3S_20P
U29-U31 = LTM8025
U32 = TLC5602A: room: CHAN1
U33 = DG419A: room: CHAN1
U34 = TLE2037A: room: CHAN1
U35 = TLC5602A: room: CHAN2
U36 = DG419A: room: CHAN2
U37 = TLE2037A: room: CHAN2
U40-U47 = uPD431000AGW-B15: room: MEM
U49 = MAX6711
U50 = NBC12429
U51 = TPS51200
XTAL1 = OSC_SEL383
Y1 = OSC4_24NC

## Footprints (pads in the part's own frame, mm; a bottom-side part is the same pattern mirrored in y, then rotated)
C-1367550-6
  round 1.1 hole 0.6: (0,0) (0,-2) (0,-4) (0,-6) (3.1,0) (3.1,-2) (3.1,-4) (3.1,-6) (6.2,0) (6.2,-2) (6.2,-4) (6.2,-6) (76.26,0) (76.26,-2) (76.26,-4) (76.26,-6) (79.36,0) (79.36,-2) (79.36,-4) (79.36,-6) (82.46,0) (82.46,-2) (82.46,-4) (82.46,-6) A1(11.755,-6.29) A2(13.785,-6.29) A3(16.835,-6.29) A4(18.865,-6.29) A5(21.915,-6.29) A6(23.945,-6.29) A7(26.995,-6.29) A8(29.025,-6.29) A9(32.075,-6.29) A10(34.105,-6.29) A11(37.155,-6.29) A12(39.185,-6.29) A13(42.235,-6.29) A14(44.265,-6.29) A15(47.315,-6.29) A16(49.345,-6.29) A17(52.395,-6.29) A18(54.425,-6.29) A19(57.475,-6.29) A20(59.505,-6.29) A21(62.555,-6.29) A22(64.585,-6.29) A23(67.635,-6.29) A24(69.665,-6.29) B1(12.77,-4.54) B2(15.31,-4.54) B3(17.85,-4.54) B4(20.39,-4.54) B5(22.93,-4.54) B6(25.47,-4.54) B7(28.01,-4.54) B8(30.55,-4.54) B9(33.09,-4.54) B10(35.63,-4.54) B11(38.17,-4.54) B12(40.71,-4.54) B13(43.25,-4.54) B14(45.79,-4.54) B15(48.33,-4.54) B16(50.87,-4.54) B17(53.41,-4.54) B18(55.95,-4.54) B19(58.49,-4.54) B20(61.03,-4.54) B21(63.57,-4.54) B22(66.11,-4.54) B23(68.65,-4.54) B24(71.19,-4.54) C1(14.295,-2.79) C2(16.325,-2.79) C3(19.375,-2.79) C4(21.405,-2.79) C5(24.455,-2.79) C6(26.485,-2.79) C7(29.535,-2.79) C8(31.565,-2.79) C9(34.615,-2.79) C10(36.645,-2.79) C11(39.695,-2.79) C12(41.725,-2.79) C13(44.775,-2.79) C14(46.805,-2.79) C15(49.855,-2.79) C16(51.885,-2.79) C17(54.935,-2.79) C18(56.965,-2.79) C19(60.015,-2.79) C20(62.045,-2.79) C21(65.095,-2.79) C22(67.125,-2.79) C23(70.175,-2.79) C24(72.205,-2.79) D1(11.755,-0.29) D2(13.785,-0.29) D3(16.835,-0.29) D4(18.865,-0.29) D5(21.915,-0.29) D6(23.945,-0.29) D7(26.995,-0.29) D8(29.025,-0.29) D9(32.075,-0.29) D10(34.105,-0.29) D11(37.155,-0.29) D12(39.185,-0.29) D13(42.235,-0.29) D14(44.265,-0.29) D15(47.315,-0.29) D16(49.345,-0.29) D17(52.395,-0.29) D18(54.425,-0.29) D19(57.475,-0.29) D20(59.505,-0.29) D21(62.555,-0.29) D22(64.585,-0.29) D23(67.635,-0.29) D24(69.665,-0.29) E1(12.77,1.46) E2(15.31,1.46) E3(17.85,1.46) E4(20.39,1.46) E5(22.93,1.46) E6(25.47,1.46) E7(28.01,1.46) E8(30.55,1.46) E9(33.09,1.46) E10(35.63,1.46) E11(38.17,1.46) E12(40.71,1.46) E13(43.25,1.46) E14(45.79,1.46) E15(48.33,1.46) E16(50.87,1.46) E17(53.41,1.46) E18(55.95,1.46) E19(58.49,1.46) E20(61.03,1.46) E21(63.57,1.46) E22(66.11,1.46) E23(68.65,1.46) E24(71.19,1.46) F1(14.295,3.21) F2(16.325,3.21) F3(19.375,3.21) F4(21.405,3.21) F5(24.455,3.21) F6(26.485,3.21) F7(29.535,3.21) F8(31.565,3.21) F9(34.615,3.21) F10(36.645,3.21) F11(39.695,3.21) F12(41.725,3.21) F13(44.775,3.21) F14(46.805,3.21) F15(49.855,3.21) F16(51.885,3.21) F17(54.935,3.21) F18(56.965,3.21) F19(60.015,3.21) F20(62.045,3.21) F21(65.095,3.21) F22(67.125,3.21) F23(70.175,3.21) F24(72.205,3.21)
C_1_1473005_1_J1
  round 0.3 hole 1.1 unplated: (0,-33.55) (0,33.25)
  rect 4.7x4.53 smd: (12,-32.565) (12,32.565)
  rect 2.05x0.38 smd: 1(-4.1,31.5) 2(4.1,31.2) 3(-4.1,30.9) 4(4.1,30.6) 5(-4.1,30.3) 6(4.1,30) 7(-4.1,29.7) 8(4.1,29.4) 9(-4.1,29.1) 10(4.1,28.8) 11(-4.1,28.5) 12(4.1,28.2) 13(-4.1,27.9) 14(4.1,27.6) 15(-4.1,27.3) 16(4.1,27) 17(-4.1,26.7) 18(4.1,26.4) 19(-4.1,26.1) 20(4.1,25.8) 21(-4.1,25.5) 22(4.1,25.2) 23(-4.1,24.9) 24(4.1,24.6) 25(-4.1,24.3) 26(4.1,24) 27(-4.1,23.7) 28(4.1,23.4) 29(-4.1,23.1) 30(4.1,22.8) 31(-4.1,22.5) 32(4.1,22.2) 33(-4.1,21.9) 34(4.1,21.6) 35(-4.1,21.3) 36(4.1,21) 37(-4.1,20.7) 38(4.1,20.4) 39(-4.1,20.1) 40(4.1,19.8) 41(-4.1,15.9) 42(4.1,15.6) 43(-4.1,15.3) 44(4.1,15) 45(-4.1,14.7) 46(4.1,14.4) 47(-4.1,14.1) 48(4.1,13.8) 49(-4.1,13.5) 50(4.1,13.2) 51(-4.1,12.9) 52(4.1,12.6) 53(-4.1,12.3) 54(4.1,12) 55(-4.1,11.7) 56(4.1,11.4) 57(-4.1,11.1) 58(4.1,10.8) 59(-4.1,10.5) 60(4.1,10.2) 61(-4.1,9.9) 62(4.1,9.6) 63(-4.1,9.3) 64(4.1,9) 65(-4.1,8.7) 66(4.1,8.4) 67(-4.1,8.1) 68(4.1,7.8) 69(-4.1,7.5) 70(4.1,7.2) 71(-4.1,6.9) 72(4.1,6.6) 73(-4.1,6.3) 74(4.1,6) 75(-4.1,5.7) 76(4.1,5.4) 77(-4.1,5.1) 78(4.1,4.8) 79(-4.1,4.5) 80(4.1,4.2) 81(-4.1,3.9) 82(4.1,3.6) 83(-4.1,3.3) 84(4.1,3) 85(-4.1,2.7) 86(4.1,2.4) 87(-4.1,2.1) 88(4.1,1.8) 89(-4.1,1.5) 90(4.1,1.2) 91(-4.1,0.9) 92(4.1,0.6) 93(-4.1,0.3) 94(4.1,0) 95(-4.1,-0.3) 96(4.1,-0.6) 97(-4.1,-0.9) 98(4.1,-1.2) 99(-4.1,-1.5) 100(4.1,-1.8) 101(-4.1,-2.1) 102(4.1,-2.4) 103(-4.1,-2.7) 104(4.1,-3) 105(-4.1,-3.3) 106(4.1,-3.6) 107(-4.1,-3.9) 108(4.1,-4.2) 109(-4.1,-4.5) 110(4.1,-4.8) 111(-4.1,-5.1) 112(4.1,-5.4) 113(-4.1,-5.7) 114(4.1,-6) 115(-4.1,-6.3) 116(4.1,-6.6) 117(-4.1,-6.9) 118(4.1,-7.2) 119(-4.1,-7.5) 120(4.1,-7.8) 121(-4.1,-8.1) 122(4.1,-8.4) 123(-4.1,-8.7) 124(4.1,-9) 125(-4.1,-9.3) 126(4.1,-9.6) 127(-4.1,-9.9) 128(4.1,-10.2) 129(-4.1,-10.5) 130(4.1,-10.8) 131(-4.1,-11.1) 132(4.1,-11.4) 133(-4.1,-11.7) 134(4.1,-12) 135(-4.1,-12.3) 136(4.1,-12.6) 137(-4.1,-12.9) 138(4.1,-13.2) 139(-4.1,-13.5) 140(4.1,-13.8) 141(-4.1,-14.1) 142(4.1,-14.4) 143(-4.1,-14.7) 144(4.1,-15) 145(-4.1,-15.3) 146(4.1,-15.6) 147(-4.1,-15.9) 148(4.1,-16.2) 149(-4.1,-16.5) 150(4.1,-16.8) 151(-4.1,-17.1) 152(4.1,-17.4) 153(-4.1,-17.7) 154(4.1,-18) 155(-4.1,-18.3) 156(4.1,-18.6) 157(-4.1,-18.9) 158(4.1,-19.2) 159(-4.1,-19.5) 160(4.1,-19.8) 161(-4.1,-20.1) 162(4.1,-20.4) 163(-4.1,-20.7) 164(4.1,-21) 165(-4.1,-21.3) 166(4.1,-21.6) 167(-4.1,-21.9) 168(4.1,-22.2) 169(-4.1,-22.5) 170(4.1,-22.8) 171(-4.1,-23.1) 172(4.1,-23.4) 173(-4.1,-23.7) 174(4.1,-24) 175(-4.1,-24.3) 176(4.1,-24.6) 177(-4.1,-24.9) 178(4.1,-25.2) 179(-4.1,-25.5) 180(4.1,-25.8) 181(-4.1,-26.1) 182(4.1,-26.4) 183(-4.1,-26.7) 184(4.1,-27) 185(-4.1,-27.3) 186(4.1,-27.6) 187(-4.1,-27.9) 188(4.1,-28.2) 189(-4.1,-28.5) 190(4.1,-28.8) 191(-4.1,-29.1) 192(4.1,-29.4) 193(-4.1,-29.7) 194(4.1,-30) 195(-4.1,-30.3) 196(4.1,-30.6) 197(-4.1,-30.9) 198(4.1,-31.2) 199(-4.1,-31.5) 200(4.1,-31.8)
CAPC1005X56N
  rect 0.6x0.65 smd: 1(-0.5,0) 2(0.5,0)
CAPC1608X86N
  rect 0.95x1 smd: 1(-0.8,0) 2(0.8,0)
CAPC2012X70N
  rect 1.15x1.45 smd: 1(-0.9,0) 2(0.9,0)
CAPC2012X71N
  rect 1.15x1.45 smd: 1(-0.9,0) 2(0.9,0)
CAPC2012X88N
  rect 1.15x1.45 smd: 1(-0.9,0) 2(0.9,0)
CAPC2012X100N
  rect 1.15x1.45 smd: 1(-0.9,0) 2(0.9,0)
CAPC2012X140N
  rect 1.15x1.45 smd: 1(-0.9,0) 2(0.9,0)
CAPMP3216X120N
  rect 1.8x1.25 smd: 1(-1.3,0) 2(1.3,0)
CAPMP3216X180N
  rect 1.8x1.25 smd: 1(-1.3,0) 2(1.3,0)
CAPMP6032X280N
  rect 2.35x2.25 smd: 1(-2.45,0) 2(2.45,0)
CAPMP7343X310N
  rect 2.35x2.45 smd: 1(-3.1,0) 2(3.1,0)
CAPMP7343X430N
  rect 2.35x2.45 smd: 1(-3.1,0) 2(3.1,0)
DRC10_2P4X1P65
  rect 0.85x0.28 smd: 1(-1.475,1) 2(-1.475,0.5) 3(-1.475,0) 4(-1.475,-0.5) 5(-1.475,-1) 6(1.475,-1) 7(1.475,-0.5) 8(1.475,0) 9(1.475,0.5) 10(1.475,1)
FT256
  round 0.45 smd: A1(-7.5,7.5) A2(-6.5,7.5) A3(-5.5,7.5) A4(-4.5,7.5) A5(-3.5,7.5) A6(-2.5,7.5) A7(-1.5,7.5) A8(-0.5,7.5) A9(0.5,7.5) A10(1.5,7.5) A11(2.5,7.5) A12(3.5,7.5) A13(4.5,7.5) A14(5.5,7.5) A15(6.5,7.5) A16(7.5,7.5) B1(-7.5,6.5) B2(-6.5,6.5) B3(-5.5,6.5) B4(-4.5,6.5) B5(-3.5,6.5) B6(-2.5,6.5) B7(-1.5,6.5) B8(-0.5,6.5) B9(0.5,6.5) B10(1.5,6.5) B11(2.5,6.5) B12(3.5,6.5) B13(4.5,6.5) B14(5.5,6.5) B15(6.5,6.5) B16(7.5,6.5) C1(-7.5,5.5) C2(-6.5,5.5) C3(-5.5,5.5) C4(-4.5,5.5) C5(-3.5,5.5) C6(-2.5,5.5) C7(-1.5,5.5) C8(-0.5,5.5) C9(0.5,5.5) C10(1.5,5.5) C11(2.5,5.5) C12(3.5,5.5) C13(4.5,5.5) C14(5.5,5.5) C15(6.5,5.5) C16(7.5,5.5) D1(-7.5,4.5) D2(-6.5,4.5) D3(-5.5,4.5) D4(-4.5,4.5) D5(-3.5,4.5) D6(-2.5,4.5) D7(-1.5,4.5) D8(-0.5,4.5) D9(0.5,4.5) D10(1.5,4.5) D11(2.5,4.5) D12(3.5,4.5) D13(4.5,4.5) D14(5.5,4.5) D15(6.5,4.5) D16(7.5,4.5) E1(-7.5,3.5) E2(-6.5,3.5) E3(-5.5,3.5) E4(-4.5,3.5) E5(-3.5,3.5) E6(-2.5,3.5) E7(-1.5,3.5) E8(-0.5,3.5) E9(0.5,3.5) E10(1.5,3.5) E11(2.5,3.5) E12(3.5,3.5) E13(4.5,3.5) E14(5.5,3.5) E15(6.5,3.5) E16(7.5,3.5) F1(-7.5,2.5) F2(-6.5,2.5) F3(-5.5,2.5) F4(-4.5,2.5) F5(-3.5,2.5) F6(-2.5,2.5) F7(-1.5,2.5) F8(-0.5,2.5) F9(0.5,2.5) F10(1.5,2.5) F11(2.5,2.5) F12(3.5,2.5) F13(4.5,2.5) F14(5.5,2.5) F15(6.5,2.5) F16(7.5,2.5) G1(-7.5,1.5) G2(-6.5,1.5) G3(-5.5,1.5) G4(-4.5,1.5) G5(-3.5,1.5) G6(-2.5,1.5) G7(-1.5,1.5) G8(-0.5,1.5) G9(0.5,1.5) G10(1.5,1.5) G11(2.5,1.5) G12(3.5,1.5) G13(4.5,1.5) G14(5.5,1.5) G15(6.5,1.5) G16(7.5,1.5) H1(-7.5,0.5) H2(-6.5,0.5) H3(-5.5,0.5) H4(-4.5,0.5) H5(-3.5,0.5) H6(-2.5,0.5) H7(-1.5,0.5) H8(-0.5,0.5) H9(0.5,0.5) H10(1.5,0.5) H11(2.5,0.5) H12(3.5,0.5) H13(4.5,0.5) H14(5.5,0.5) H15(6.5,0.5) H16(7.5,0.5) J1(-7.5,-0.5) J2(-6.5,-0.5) J3(-5.5,-0.5) J4(-4.5,-0.5) J5(-3.5,-0.5) J6(-2.5,-0.5) J7(-1.5,-0.5) J8(-0.5,-0.5) J9(0.5,-0.5) J10(1.5,-0.5) J11(2.5,-0.5) J12(3.5,-0.5) J13(4.5,-0.5) J14(5.5,-0.5) J15(6.5,-0.5) J16(7.5,-0.5) K1(-7.5,-1.5) K2(-6.5,-1.5) K3(-5.5,-1.5) K4(-4.5,-1.5) K5(-3.5,-1.5) K6(-2.5,-1.5) K7(-1.5,-1.5) K8(-0.5,-1.5) K9(0.5,-1.5) K10(1.5,-1.5) K11(2.5,-1.5) K12(3.5,-1.5) K13(4.5,-1.5) K14(5.5,-1.5) K15(6.5,-1.5) K16(7.5,-1.5) L1(-7.5,-2.5) L2(-6.5,-2.5) L3(-5.5,-2.5) L4(-4.5,-2.5) L5(-3.5,-2.5) L6(-2.5,-2.5) L7(-1.5,-2.5) L8(-0.5,-2.5) L9(0.5,-2.5) L10(1.5,-2.5) L11(2.5,-2.5) L12(3.5,-2.5) L13(4.5,-2.5) L14(5.5,-2.5) L15(6.5,-2.5) L16(7.5,-2.5) M1(-7.5,-3.5) M2(-6.5,-3.5) M3(-5.5,-3.5) M4(-4.5,-3.5) M5(-3.5,-3.5) M6(-2.5,-3.5) M7(-1.5,-3.5) M8(-0.5,-3.5) M9(0.5,-3.5) M10(1.5,-3.5) M11(2.5,-3.5) M12(3.5,-3.5) M13(4.5,-3.5) M14(5.5,-3.5) M15(6.5,-3.5) M16(7.5,-3.5) N1(-7.5,-4.5) N2(-6.5,-4.5) N3(-5.5,-4.5) N4(-4.5,-4.5) N5(-3.5,-4.5) N6(-2.5,-4.5) N7(-1.5,-4.5) N8(-0.5,-4.5) N9(0.5,-4.5) N10(1.5,-4.5) N11(2.5,-4.5) N12(3.5,-4.5) N13(4.5,-4.5) N14(5.5,-4.5) N15(6.5,-4.5) N16(7.5,-4.5) P1(-7.5,-5.5) P2(-6.5,-5.5) P3(-5.5,-5.5) P4(-4.5,-5.5) P5(-3.5,-5.5) P6(-2.5,-5.5) P7(-1.5,-5.5) P8(-0.5,-5.5) P9(0.5,-5.5) P10(1.5,-5.5) P11(2.5,-5.5) P12(3.5,-5.5) P13(4.5,-5.5) P14(5.5,-5.5) P15(6.5,-5.5) P16(7.5,-5.5) R1(-7.5,-6.5) R2(-6.5,-6.5) R3(-5.5,-6.5) R4(-4.5,-6.5) R5(-3.5,-6.5) R6(-2.5,-6.5) R7(-1.5,-6.5) R8(-0.5,-6.5) R9(0.5,-6.5) R10(1.5,-6.5) R11(2.5,-6.5) R12(3.5,-6.5) R13(4.5,-6.5) R14(5.5,-6.5) R15(6.5,-6.5) R16(7.5,-6.5) T1(-7.5,-7.5) T2(-6.5,-7.5) T3(-5.5,-7.5) T4(-4.5,-7.5) T5(-3.5,-7.5) T6(-2.5,-7.5) T7(-1.5,-7.5) T8(-0.5,-7.5) T9(0.5,-7.5) T10(1.5,-7.5) T11(2.5,-7.5) T12(3.5,-7.5) T13(4.5,-7.5) T14(5.5,-7.5) T15(6.5,-7.5) T16(7.5,-7.5)
IND_CENTRAL_1008
  rect 1.02x2.54 smd: 1(-1.145,0) 2(1.145,0)
INDC1005X60N
  rect 0.6x0.7 smd: 1(-0.5,0) 2(0.5,0)
INDC2520X220N
  rect 0.95x2.3 smd: 1(-1.25,0) 2(1.25,0)
LEDC2012X120N
  rect 1x1.4 smd: A(0.9,0) C(-0.9,0)
LTUMODULE7X11
  custom 0.159x0.159 smd: A1(-3.81,6.35)
  rect 0.635x0.635 smd: A2(-2.54,6.35) A3(-1.27,6.35) A4(0,6.35) A5(1.27,6.35) A6(2.54,6.35) A7(3.81,6.35) B1(-3.81,5.08) B2(-2.54,5.08) B3(-1.27,5.08) B4(0,5.08) B5(1.27,5.08) B6(2.54,5.08) B7(3.81,5.08) C1(-3.81,3.81) C2(-2.54,3.81) C3(-1.27,3.81) C4(0,3.81) C5(1.27,3.81) C6(2.54,3.81) C7(3.81,3.81) D1(-3.81,2.54) D2(-2.54,2.54) D3(-1.27,2.54) D4(0,2.54) D5(1.27,2.54) D6(2.54,2.54) D7(3.81,2.54) E1(-3.81,1.27) E2(-2.54,1.27) E3(-1.27,1.27) E4(0,1.27) E5(1.27,1.27) E6(2.54,1.27) E7(3.81,1.27) F1(-3.81,0) F2(-2.54,0) F3(-1.27,0) F4(0,0) F5(1.27,0) F6(2.54,0) F7(3.81,0) G1(-3.81,-1.27) G2(-2.54,-1.27) G3(-1.27,-1.27) G4(0,-1.27) G5(1.27,-1.27) G6(2.54,-1.27) G7(3.81,-1.27) H5(1.27,-2.54) H6(2.54,-2.54) H7(3.81,-2.54) J1(-3.81,-3.81) J2(-2.54,-3.81) J3(-1.27,-3.81) J5(1.27,-3.81) J6(2.54,-3.81) J7(3.81,-3.81) K1(-3.81,-5.08) K2(-2.54,-5.08) K3(-1.27,-5.08) K5(1.27,-5.08) K6(2.54,-5.08) K7(3.81,-5.08) L1(-3.81,-6.35) L2(-2.54,-6.35) L3(-1.27,-6.35) L5(1.27,-6.35) L6(2.54,-6.35) L7(3.81,-6.35)
MT47H128M
  round 1 smd: (-4.85,-7.1) (4.85,7.1)
  round 0.45 smd: A1(-3.2,5.6) A2(-2.4,5.6) A3(-1.6,5.6) A7(1.6,5.6) A8(2.4,5.6) A9(3.2,5.6) B1(-3.2,4.8) B2(-2.4,4.8) B3(-1.6,4.8) B7(1.6,4.8) B8(2.4,4.8) B9(3.2,4.8) C1(-3.2,4) C2(-2.4,4) C3(-1.6,4) C7(1.6,4) C8(2.4,4) C9(3.2,4) D1(-3.2,3.2) D2(-2.4,3.2) D3(-1.6,3.2) D7(1.6,3.2) D8(2.4,3.2) D9(3.2,3.2) E1(-3.2,2.4) E2(-2.4,2.4) E3(-1.6,2.4) E7(1.6,2.4) E8(2.4,2.4) E9(3.2,2.4) F1(-3.2,1.6) F2(-2.4,1.6) F3(-1.6,1.6) F7(1.6,1.6) F8(2.4,1.6) F9(3.2,1.6) G1(-3.2,0.8) G2(-2.4,0.8) G3(-1.6,0.8) G7(1.6,0.8) G8(2.4,0.8) G9(3.2,0.8) H1(-3.2,0) H2(-2.4,0) H3(-1.6,0) H7(1.6,0) H8(2.4,0) H9(3.2,0) J1(-3.2,-0.8) J2(-2.4,-0.8) J3(-1.6,-0.8) J7(1.6,-0.8) J8(2.4,-0.8) J9(3.2,-0.8) K2(-2.4,-1.6) K3(-1.6,-1.6) K7(1.6,-1.6) K8(2.4,-1.6) K9(3.2,-1.6) L1(-3.2,-2.4) L2(-2.4,-2.4) L3(-1.6,-2.4) L7(1.6,-2.4) L8(2.4,-2.4) M2(-2.4,-3.2) M3(-1.6,-3.2) M7(1.6,-3.2) M8(2.4,-3.2) M9(3.2,-3.2) N1(-3.2,-4) N2(-2.4,-4) N3(-1.6,-4) N7(1.6,-4) N8(2.4,-4) P2(-2.4,-4.8) P3(-1.6,-4.8) P7(1.6,-4.8) P8(2.4,-4.8) P9(3.2,-4.8) R1(-3.2,-5.6) R2(-2.4,-5.6) R3(-1.6,-5.6) R7(1.6,-5.6) R8(2.4,-5.6)
OSCCC350X600X120N
  rect 1.45x1.95 smd: 1(-1.4,2.376) 2(-1.4,-2.374) 3(1.4,-2.374) 4(1.4,2.376)
OSCSC254P500X700X200-6N
  rect 1.95x1.6 smd: 1(-2.05,2.541) 2(-2.05,0.001) 3(-2.05,-2.539) 4(2.05,-2.539) 5(2.05,0.001) 6(2.05,2.541)
QFN50P500X500X100-33N
  rect 0.8x0.3 smd: 1(-2.475,1.75) 2(-2.475,1.25) 3(-2.475,0.75) 4(-2.475,0.25) 5(-2.475,-0.25) 6(-2.475,-0.75) 7(-2.475,-1.25) 8(-2.475,-1.75) 17(2.475,-1.75) 18(2.475,-1.25) 19(2.475,-0.75) 20(2.475,-0.25) 21(2.475,0.25) 22(2.475,0.75) 23(2.475,1.25) 24(2.475,1.75)
  rect 0.3x0.8 smd: 9(-1.75,-2.475) 10(-1.25,-2.475) 11(-0.75,-2.475) 12(-0.25,-2.475) 13(0.25,-2.475) 14(0.75,-2.475) 15(1.25,-2.475) 16(1.75,-2.475) 25(1.75,2.475) 26(1.25,2.475) 27(0.75,2.475) 28(0.25,2.475) 29(-0.25,2.475) 30(-0.75,2.475) 31(-1.25,2.475) 32(-1.75,2.475)
  rect 3.2x3.2 smd: 33(0,0)
RESC0603X26N
  rect 0.45x0.4 smd: 1(-0.35,0) 2(0.35,0)
RESC0603X30N
  rect 0.45x0.4 smd: 1(-0.35,0) 2(0.35,0)
RESC1608X50N
  rect 0.85x1 smd: 1(-0.75,0) 2(0.75,0)
RESC1608X55N
  rect 0.9x1 smd: 1(-0.8,0) 2(0.8,0)
RESC2012X50N
  rect 0.95x1.45 smd: 1(-1,0) 2(1,0)
RESC2012X60N
  rect 0.95x1.4 smd: 1(-1,0) 2(1,0)
RESC2012X70N
  rect 1.05x1.4 smd: 1(-0.95,0) 2(0.95,0)
RESC3225X70N
  rect 1.1x2.7 smd: 1(-1.5,0) 2(1.5,0)
RESNET_8
  rect 0.55x0.2 smd: 1(-0.4,0.6) 2(-0.4,0.2) 3(-0.4,-0.2) 4(-0.4,-0.6) 5(0.4,-0.6) 6(0.4,-0.2) 7(0.4,0.2) 8(0.4,0.6)
SAMTEC_TST-107-XX-X-D
  rect 1.6x1.6 hole 0.95: 1(0,0)
  round 1.6 hole 0.95: 2(0,2.54) 3(2.54,0) 4(2.54,2.54) 5(5.08,0) 6(5.08,2.54) 7(7.62,0) 8(7.62,2.54) 9(10.16,0) 10(10.16,2.54) 11(12.7,0) 12(12.7,2.54) 13(15.24,0) 14(15.24,2.54)
SMB_90
  round 1.8 hole 1.2: 1(0,0)
  round 2.3 hole 1.7: 2(-2.54,2.54) 3(2.54,2.54) 4(-2.54,-2.54) 5(2.54,-2.54)
SOG0508WG244L225
  rect 0.635x2.388 smd: 1(0,0)
  oval 0.635x2.388 smd: 2(1.27,0) 3(2.54,0) 4(3.81,0) 5(3.81,4.978) 6(2.54,4.978) 7(1.27,4.978) 8(0,4.978)
SOIC127P600X175-8N
  rect 1.55x0.6 smd: 1(-2.7,1.905) 2(-2.7,0.635) 3(-2.7,-0.635) 4(-2.7,-1.905) 5(2.7,-1.905) 6(2.7,-0.635) 7(2.7,0.635) 8(2.7,1.905)
SOIC127P1028X265-20N
  oval 1.75x0.6 smd: 1(-4.7,5.715) 2(-4.7,4.445) 3(-4.7,3.175) 4(-4.7,1.905) 5(-4.7,0.635) 6(-4.7,-0.635) 7(-4.7,-1.905) 8(-4.7,-3.175) 9(-4.7,-4.445) 10(-4.7,-5.715) 11(4.7,-5.715) 12(4.7,-4.445) 13(4.7,-3.175) 14(4.7,-1.905) 15(4.7,-0.635) 16(4.7,0.635) 17(4.7,1.905) 18(4.7,3.175) 19(4.7,4.445) 20(4.7,5.715)
SOIC127P1032X265-20AN
  oval 1.85x0.6 smd: 1(-4.75,5.715) 2(-4.75,4.445) 3(-4.75,3.175) 4(-4.75,1.905) 5(-4.75,0.635) 6(-4.75,-0.635) 7(-4.75,-1.905) 8(-4.75,-3.175) 9(-4.75,-4.445) 10(-4.75,-5.715) 11(4.75,-5.715) 12(4.75,-4.445) 13(4.75,-3.175) 14(4.75,-1.905) 15(4.75,-0.635) 16(4.75,0.635) 17(4.75,1.905) 18(4.75,3.175) 19(4.75,4.445) 20(4.75,5.715)
SOIC254P1077X800-8M
  oval 3.05x2 smd: 1(-4.6,3.81) 2(-4.6,1.27) 3(-4.6,-1.27) 4(-4.6,-3.81) 5(5.685,-3.81) 6(5.685,-1.27) 7(5.685,1.27) 8(5.685,3.81)
SOJ127P866X375-32N
  oval 2.45x0.65 smd: 1(-3.55,9.525) 2(-3.55,8.255) 3(-3.55,6.985) 4(-3.55,5.715) 5(-3.55,4.445) 6(-3.55,3.175) 7(-3.55,1.905) 8(-3.55,0.635) 9(-3.55,-0.635) 10(-3.55,-1.905) 11(-3.55,-3.175) 12(-3.55,-4.445) 13(-3.55,-5.715) 14(-3.55,-6.985) 15(-3.55,-8.255) 16(-3.55,-9.525) 17(3.55,-9.525) 18(3.55,-8.255) 19(3.55,-6.985) 20(3.55,-5.715) 21(3.55,-4.445) 22(3.55,-3.175) 23(3.55,-1.905) 24(3.55,-0.635) 25(3.55,0.635) 26(3.55,1.905) 27(3.55,3.175) 28(3.55,4.445) 29(3.55,5.715) 30(3.55,6.985) 31(3.55,8.255) 32(3.55,9.525)
SOP50P810X110-48N
  rect 1.45x0.3 smd: 1(-3.8,5.75) 2(-3.8,5.25) 3(-3.8,4.75) 4(-3.8,4.25) 5(-3.8,3.75) 6(-3.8,3.25) 7(-3.8,2.75) 8(-3.8,2.25) 9(-3.8,1.75) 10(-3.8,1.25) 11(-3.8,0.75) 12(-3.8,0.25) 13(-3.8,-0.25) 14(-3.8,-0.75) 15(-3.8,-1.25) 16(-3.8,-1.75) 17(-3.8,-2.25) 18(-3.8,-2.75) 19(-3.8,-3.25) 20(-3.8,-3.75) 21(-3.8,-4.25) 22(-3.8,-4.75) 23(-3.8,-5.25) 24(-3.8,-5.75) 25(3.8,-5.75) 26(3.8,-5.25) 27(3.8,-4.75) 28(3.8,-4.25) 29(3.8,-3.75) 30(3.8,-3.25) 31(3.8,-2.75) 32(3.8,-2.25) 33(3.8,-1.75) 34(3.8,-1.25) 35(3.8,-0.75) 36(3.8,-0.25) 37(3.8,0.25) 38(3.8,0.75) 39(3.8,1.25) 40(3.8,1.75) 41(3.8,2.25) 42(3.8,2.75) 43(3.8,3.25) 44(3.8,3.75) 45(3.8,4.25) 46(3.8,4.75) 47(3.8,5.25) 48(3.8,5.75)
SOP65P780X200-28N
  rect 1.75x0.45 smd: 1(-3.6,4.225) 2(-3.6,3.575) 3(-3.6,2.925) 4(-3.6,2.275) 5(-3.6,1.625) 6(-3.6,0.975) 7(-3.6,0.325) 8(-3.6,-0.325) 9(-3.6,-0.975) 10(-3.6,-1.625) 11(-3.6,-2.275) 12(-3.6,-2.925) 13(-3.6,-3.575) 14(-3.6,-4.225) 15(3.6,-4.225) 16(3.6,-3.575) 17(3.6,-2.925) 18(3.6,-2.275) 19(3.6,-1.625) 20(3.6,-0.975) 21(3.6,-0.325) 22(3.6,0.325) 23(3.6,0.975) 24(3.6,1.625) 25(3.6,2.275) 26(3.6,2.925) 27(3.6,3.575) 28(3.6,4.225)
SOT95P230X109-3N
  rect 0.95x0.6 smd: 1(-1.15,0.95) 2(-1.15,-0.95) 3(1.15,0)
SOT95P240X114-3N
  rect 0.95x0.6 smd: 1(-1.15,0.95) 2(-1.15,-0.95) 3(1.15,0)
SOT343N
  rect 1.1x0.45 smd: 1(-0.9,0.65) 3(0.9,-0.65) 4(0.9,0.65)
  rect 1.1x0.8 smd: 2(-0.9,-0.5)
SW_EVQ-PH_NO_GND
  rect 1x3.2 smd: 1(-2,3.4) 2(2,3.4) 3(-2,-3.4) 4(2,-3.4)
TO92
  oval 2x1 hole 0.8: 1(0,0) 2(0,-1.27) 3(0,-2.54)
TO99
  round 1.575 hole 1: 1(0,0) 2(1.803,0.737) 3(2.54,2.54) 4(1.803,4.343) 5(0,5.08) 6(-1.803,4.343) 7(-2.54,2.54) 8(-1.803,0.737)
TO230P950X240-3N
  rect 2.3x0.95 smd: 1(-4.1,2.3) 2(-4.1,-2.3)
  rect 6.9x5.55 smd: 3(1.8,0)
TO254P1410X464-4N
  rect 3x1.05 smd: 1(-6,2.54) 2(-6,0) 3(-6,-2.54)
  rect 6.9x10.5 smd: 4(4.1,0)
TOROID01_3
  round 1.397 hole 0.8: 1(0,0) 2(2.54,0) 3(5.08,0)
unnamed#2
  oval 3x2 hole 2x1: (-3.175,0) (3.175,0)
  round 2 hole 0.8: (0,0)
unnamed#3
  round 0.635 hole 3.175 unplated: (0,0)
unnamed#4
  round 1.397 hole 0.8: (13.462,8.382) (44.45,19.05) (50.546,6.604)
USB3A_FEMALE
  round 1.1 hole 0.8: 1(-3.5,-1.5) 2(-1,-1.5) 3(1,-1.5) 4(3.5,-1.5) 5(4,0) 6(2,0) 7(0,0) 8(-2,0) 9(-4,0)
  round 2.9 hole 2.3: 10(-6.57,-3.5) 11(6.57,-3.5)
XCF01SVOG20
  rect 1.5x0.45 smd: 1(-2.9,2.925) 2(-2.9,2.275) 3(-2.9,1.625) 4(-2.9,0.975) 5(-2.9,0.325) 6(-2.9,-0.325) 7(-2.9,-0.975) 8(-2.9,-1.625) 9(-2.9,-2.275) 10(-2.9,-2.925) 11(2.9,-2.925) 12(2.9,-2.275) 13(2.9,-1.625) 14(2.9,-0.975) 15(2.9,-0.325) 16(2.9,0.325) 17(2.9,0.975) 18(2.9,1.625) 19(2.9,2.275) 20(2.9,2.925)

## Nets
0V9: C2011.1 C2012.1 C2013.1 P1.2 U12.J2 U13.J2 U51.3 U51.5(VOSNS)
1V2: C63.1 C125.1 C126.1 C127.1 C128.1 C129.1 C130.1 C131.1 C132.1 C133.1 C178.1 C179.1 C180.1 C181.1 C182.1 C183.1 C184.1 C185.1 C186.1 P1.4 U1.G7 U1.G9 U1.H8 U1.H10 U1.J7 U1.J9 U1.K8 U1.K10 U2.G7 U2.G9 U2.H8 U2.H10 U2.J7 U2.J9 U2.K8 U2.K10 U29.A1 U29.A2 U29.A3 U29.A4 U29.B1 U29.B2 U29.B3 U29.B4 U29.C1 U29.C2 U29.C3 U29.C4 U29.D1 U29.D2 U29.D3 U29.D4(VOUT#D4)
1V8: C73.1 C74.1 C75.1 C76.1 C77.1 C78.1 C79.1 C80.1 C81.1 C82.1 C83.1 C84.1 C85.1 C86.1 C87.1 C88.1 C105.1 C106.1 C134.1 C135.1 C136.1 C137.1 C138.1 C139.1 C140.1 C141.1 C142.1 C143.1 C187.1 C188.1 C189.1 C190.1 C191.1 C192.1 C193.1 C194.1 C195.1 C196.1 C2014.1 C2015.1 P1.6 R2010.1 U2.B4 U2.B9 U2.B13 U2.D2 U2.G4 U2.J2 U2.K4 U2.N2(VCCO_3#N2) U2.N7 U2.N15 U2.R13 U12.A1 U12.A9 U12.C1 U12.C3 U12.C7 U12.C9 U12.E1 U12.E9 U12.G1 U12.G7 U12.G9 U12.J1 U12.J9 U12.M9 U12.R1 U13.A1 U13.A9 U13.C1 U13.C3 U13.C7 U13.C9 U13.E1 U13.E9 U13.G1 U13.G7 U13.G9 U13.J1 U13.J9 U13.M9 U13.R1 U51.2
2V5: C65.1 C89.1 C90.1 C91.1 C92.1 C93.1 C94.1 C95.1 C96.1 C97.1 C98.1 C99.1 C100.1 C101.1 C102.1 C103.1 C104.1 C116.1 C117.1 C118.1 C119.1 C120.1 C121.1 C122.1 C123.1 C124.1 C144.1 C145.1 C146.1 C147.1 C148.1 C149.1 C150.1 C151.1 C152.1 C153.1 C154.1 C155.1 C156.1 C157.1 C158.1 C159.1 C169.1 C170.1 C171.1 C172.1 C173.1 C174.1 C175.1 C176.1 C177.1 P1.14 U1.D2 U1.E5 U1.F8 U1.F11 U1.G4 U1.G10 U1.H6 U1.J2 U1.J10 U1.K4 U1.L6 U1.L9 U1.N2(VCCO_3#N2) U1.N7 U1.N10 U1.R4 U1.R8 U1.R13 U2.D7 U2.D10 U2.D15 U2.E5 U2.F8 U2.F11 U2.G10 U2.H6 U2.J10 U2.L6 U2.L9 U2.N10 U2.R4 U2.R8 U10.19(VCCO) U10.20 U11.19(VCCO) U11.20 U30.A1 U30.A2 U30.A3 U30.A4 U30.B1 U30.B2 U30.B3 U30.B4 U30.C1 U30.C2 U30.C3 U30.C4 U30.D1 U30.D2 U30.D3 U30.D4(VOUT#D4)
3V3: C67.1 C107.1 C108.1 C109.1 C110.1 C111.1 C112.1 C113.1 C114.1 C115.1 C160.1 C161.1 C162.1 C163.1 C164.1 C165.1 C166.1 C167.1 C168.1 P1.12 R2012.1 RN1.5(2) RN1.6 RN1.7 RN1.8 U1.B4 U1.B9 U1.B13 U1.D7 U1.D10 U1.D15 U1.G13 U1.J15 U1.K13 U1.N15 U2.G13 U2.J15 U2.K13 U10.18 U11.18 U29.H5 U30.H5 U31.A1 U31.A2 U31.A3 U31.A4 U31.B1 U31.B2 U31.B3 U31.B4 U31.C1 U31.C2 U31.C3 U31.C4 U31.D1 U31.D2 U31.D3 U31.D4(VOUT#D4) U51.7 U51.10
5V: C23.1 C24.1 C25.1 C26.1 C27.1 C28.1 C29.1 C30.1 U4.6(DVDD#6) U4.11 U4.18 U4.23 U5.3 XTAL1.1 XTAL1.2 XTAL1.6(VCC)
GND EARTH: C1.2 C2.2 J1.2 J1.3 J1.4 J1.5(SHIELD3) J2.2 J2.3 J2.4 J2.5(SHIELD3) J3.2 J3.3 J3.4 J3.5(SHIELD3) SW1.5(B4) SW1.6 SW1.7 SW1.8
V12N: J6.A3 J6.A4 J6.D3 J6.D4 U33.7 U34.4(VMIN) U36.7 U37.4(VMIN)
VCC: C44.1 C45.1 C46.1 C47.1 C48.1 C49.1 C50.1 C51.1 C52.1 C53.1 C54.1 C55.1 C197.1 C200.1 C2006.1 C2007.2 J5.1(VBUS) J6.A23 J6.A24 J6.D23 J6.D24 J7.31 J7.32 J7.33 J7.34 J7.35 J7.36 J7.37 J7.38 J7.81 J7.82 J7.83 J7.84 J7.85 J7.86 J7.87 J7.88 J7.131 J7.132 J7.133 J7.134 J7.135 J7.136 J7.137 J7.138 J7.181 J7.182 J7.183 J7.184 J7.185 J7.186 J7.187 J7.188 L8.1 L10.1 R27.1 R28.1 R29.1 R30.1 R2006.1 R2007.2 R2008.1 U6.7 U6.18 U6.31 U6.42 U7.20(VCC) U8.7 U8.18 U8.31 U8.42 U9.7 U9.18 U9.31 U9.42 U22.20(VCC) U32.2 U32.9(VD2) U35.2 U35.9(VD2) U38.20(VCC) U39.20(VCC) U40.32 U41.32 U42.32 U43.32 U44.32 U45.32 U46.32 U47.32 U48.20(VCC) U49.4(VCC) U50.27 U50.28 U50.32
